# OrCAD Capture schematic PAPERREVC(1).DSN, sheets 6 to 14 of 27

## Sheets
6 PAGE1 (6): block FPGA32/ADC1, another copy of sheet 4
7 PAGE1 (7): size A; title: SNAP, BOARD LAYOUT and Change Log
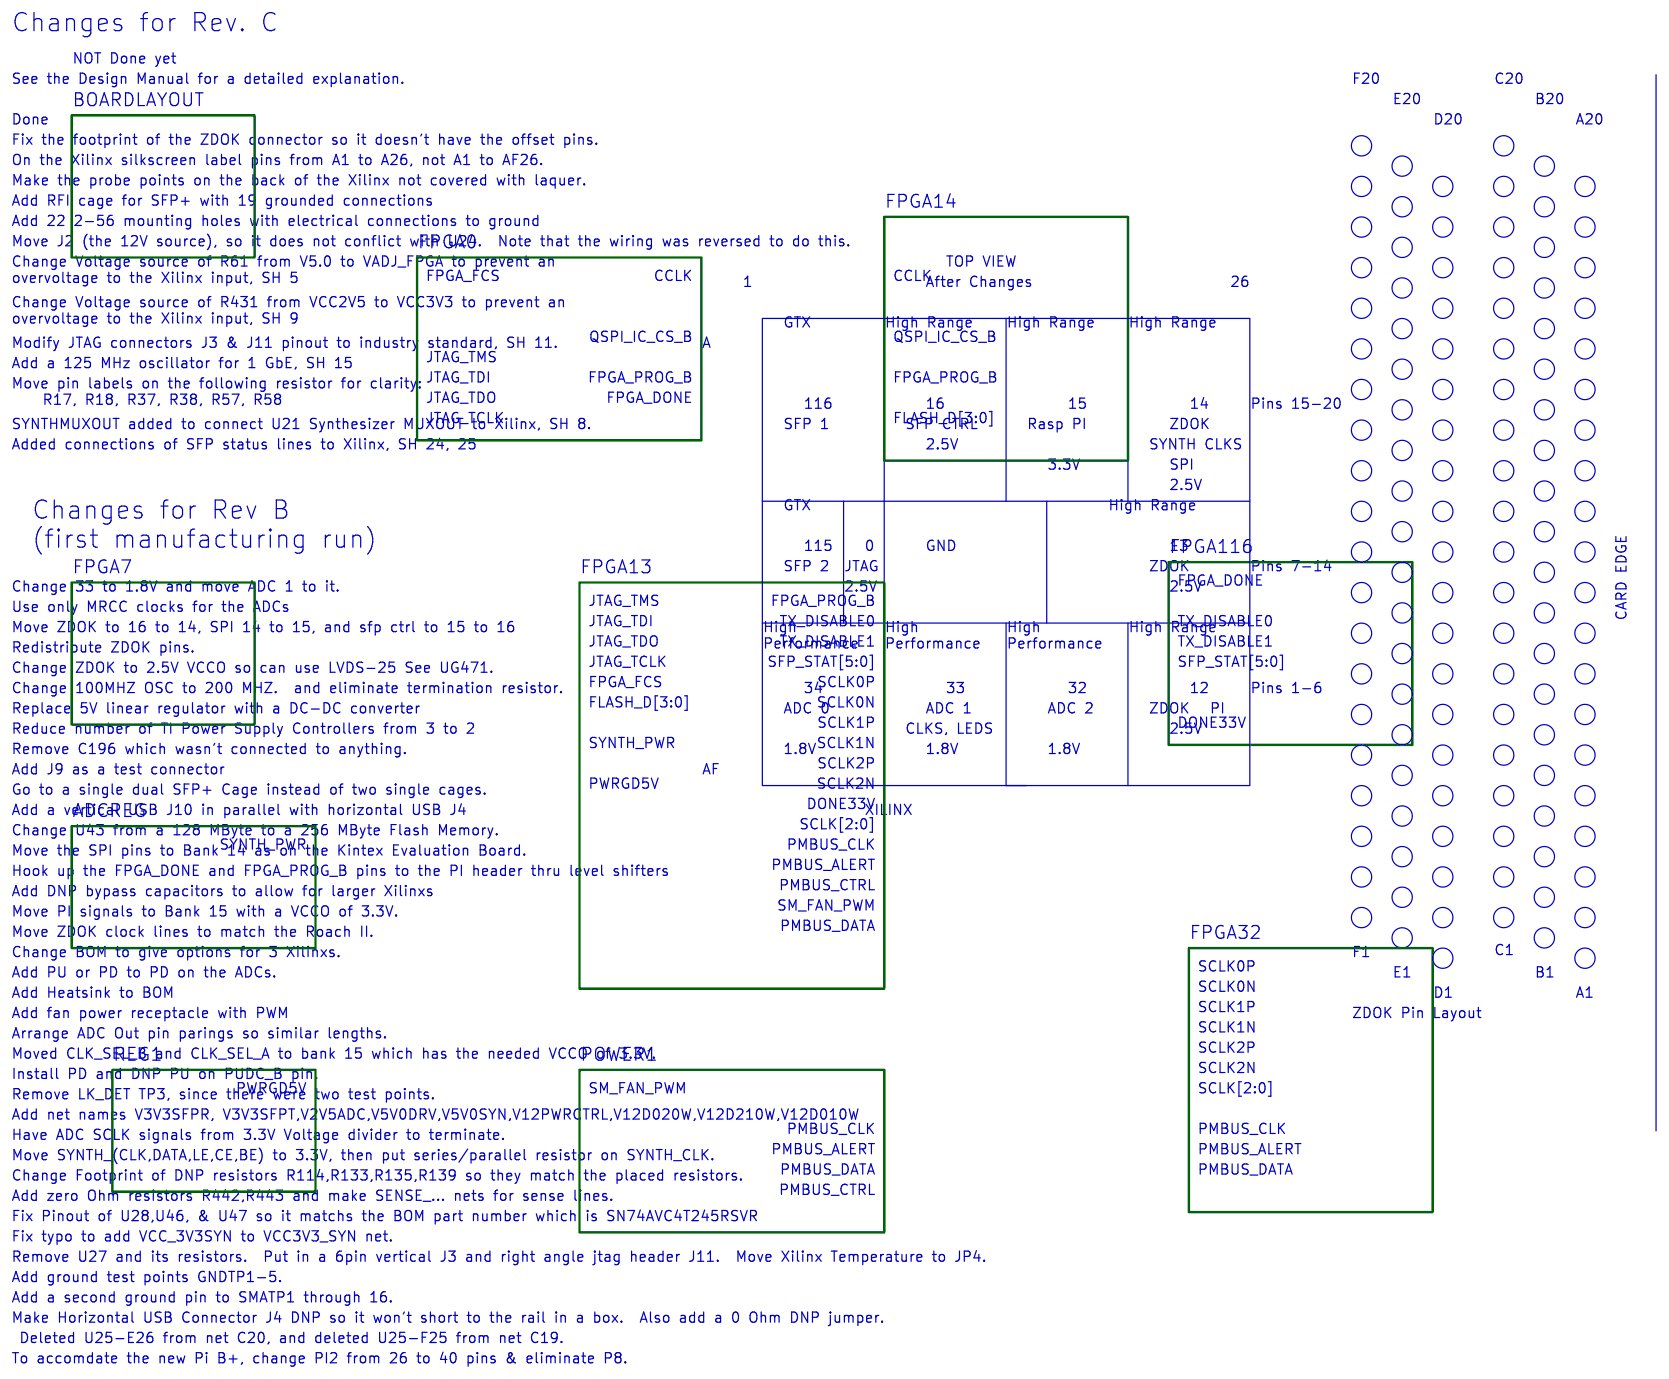
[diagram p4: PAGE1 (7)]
8 PAGE1 (8): size A; title: SNAP, FPGA Regulators; company: NRAO; block REG1
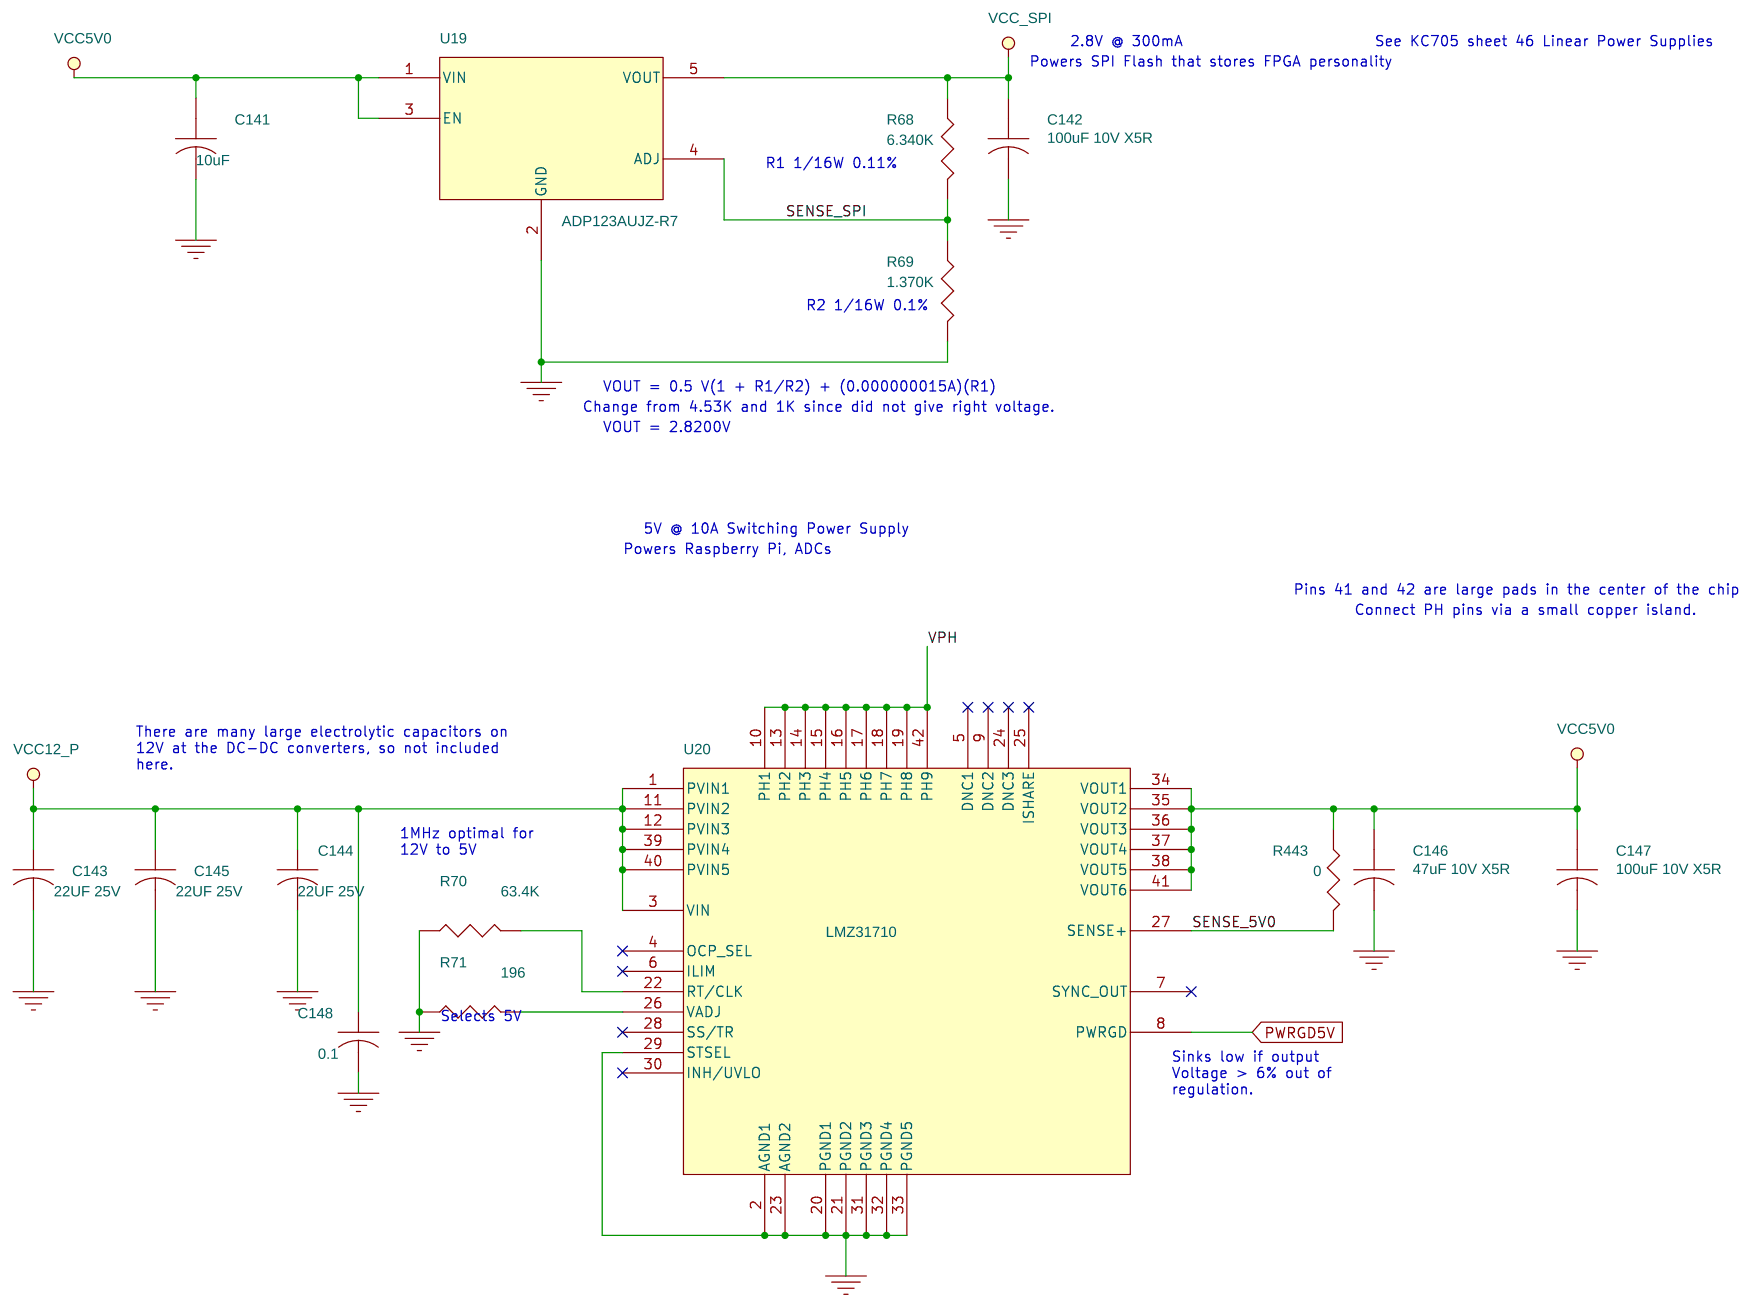
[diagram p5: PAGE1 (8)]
9 PAGE1 (9): size B; title: SNAP, FPGA POWER; block FPGA7
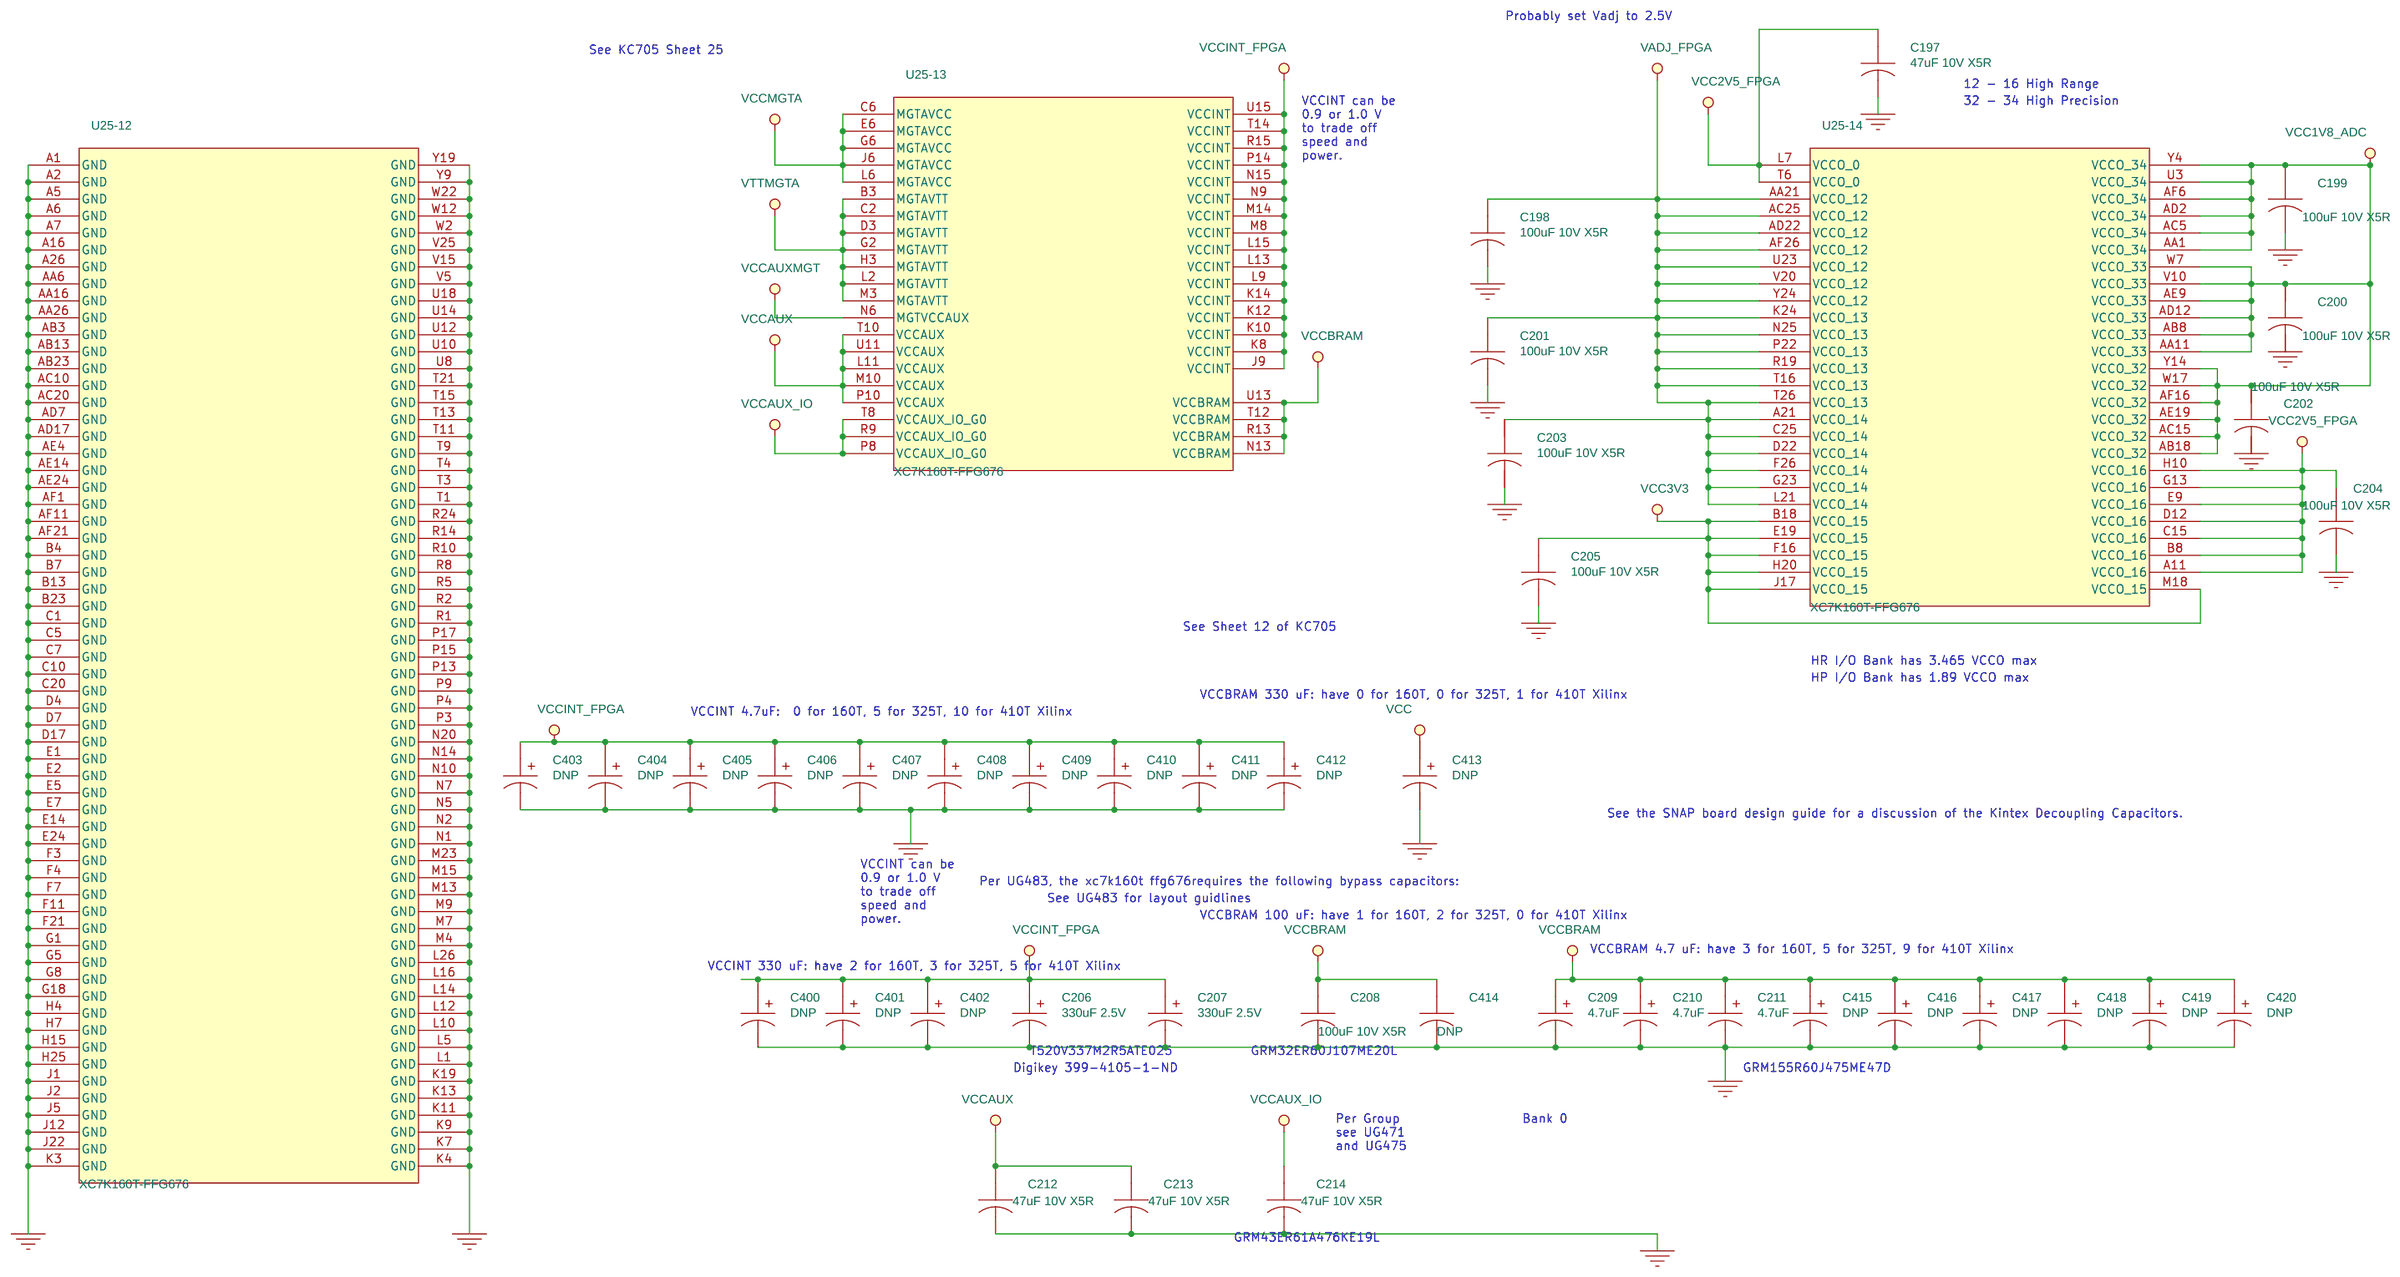
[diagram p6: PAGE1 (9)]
10 PAGE1 (10): size B; title: SNAP, SFP+ Connector and Cage; block FPGA116
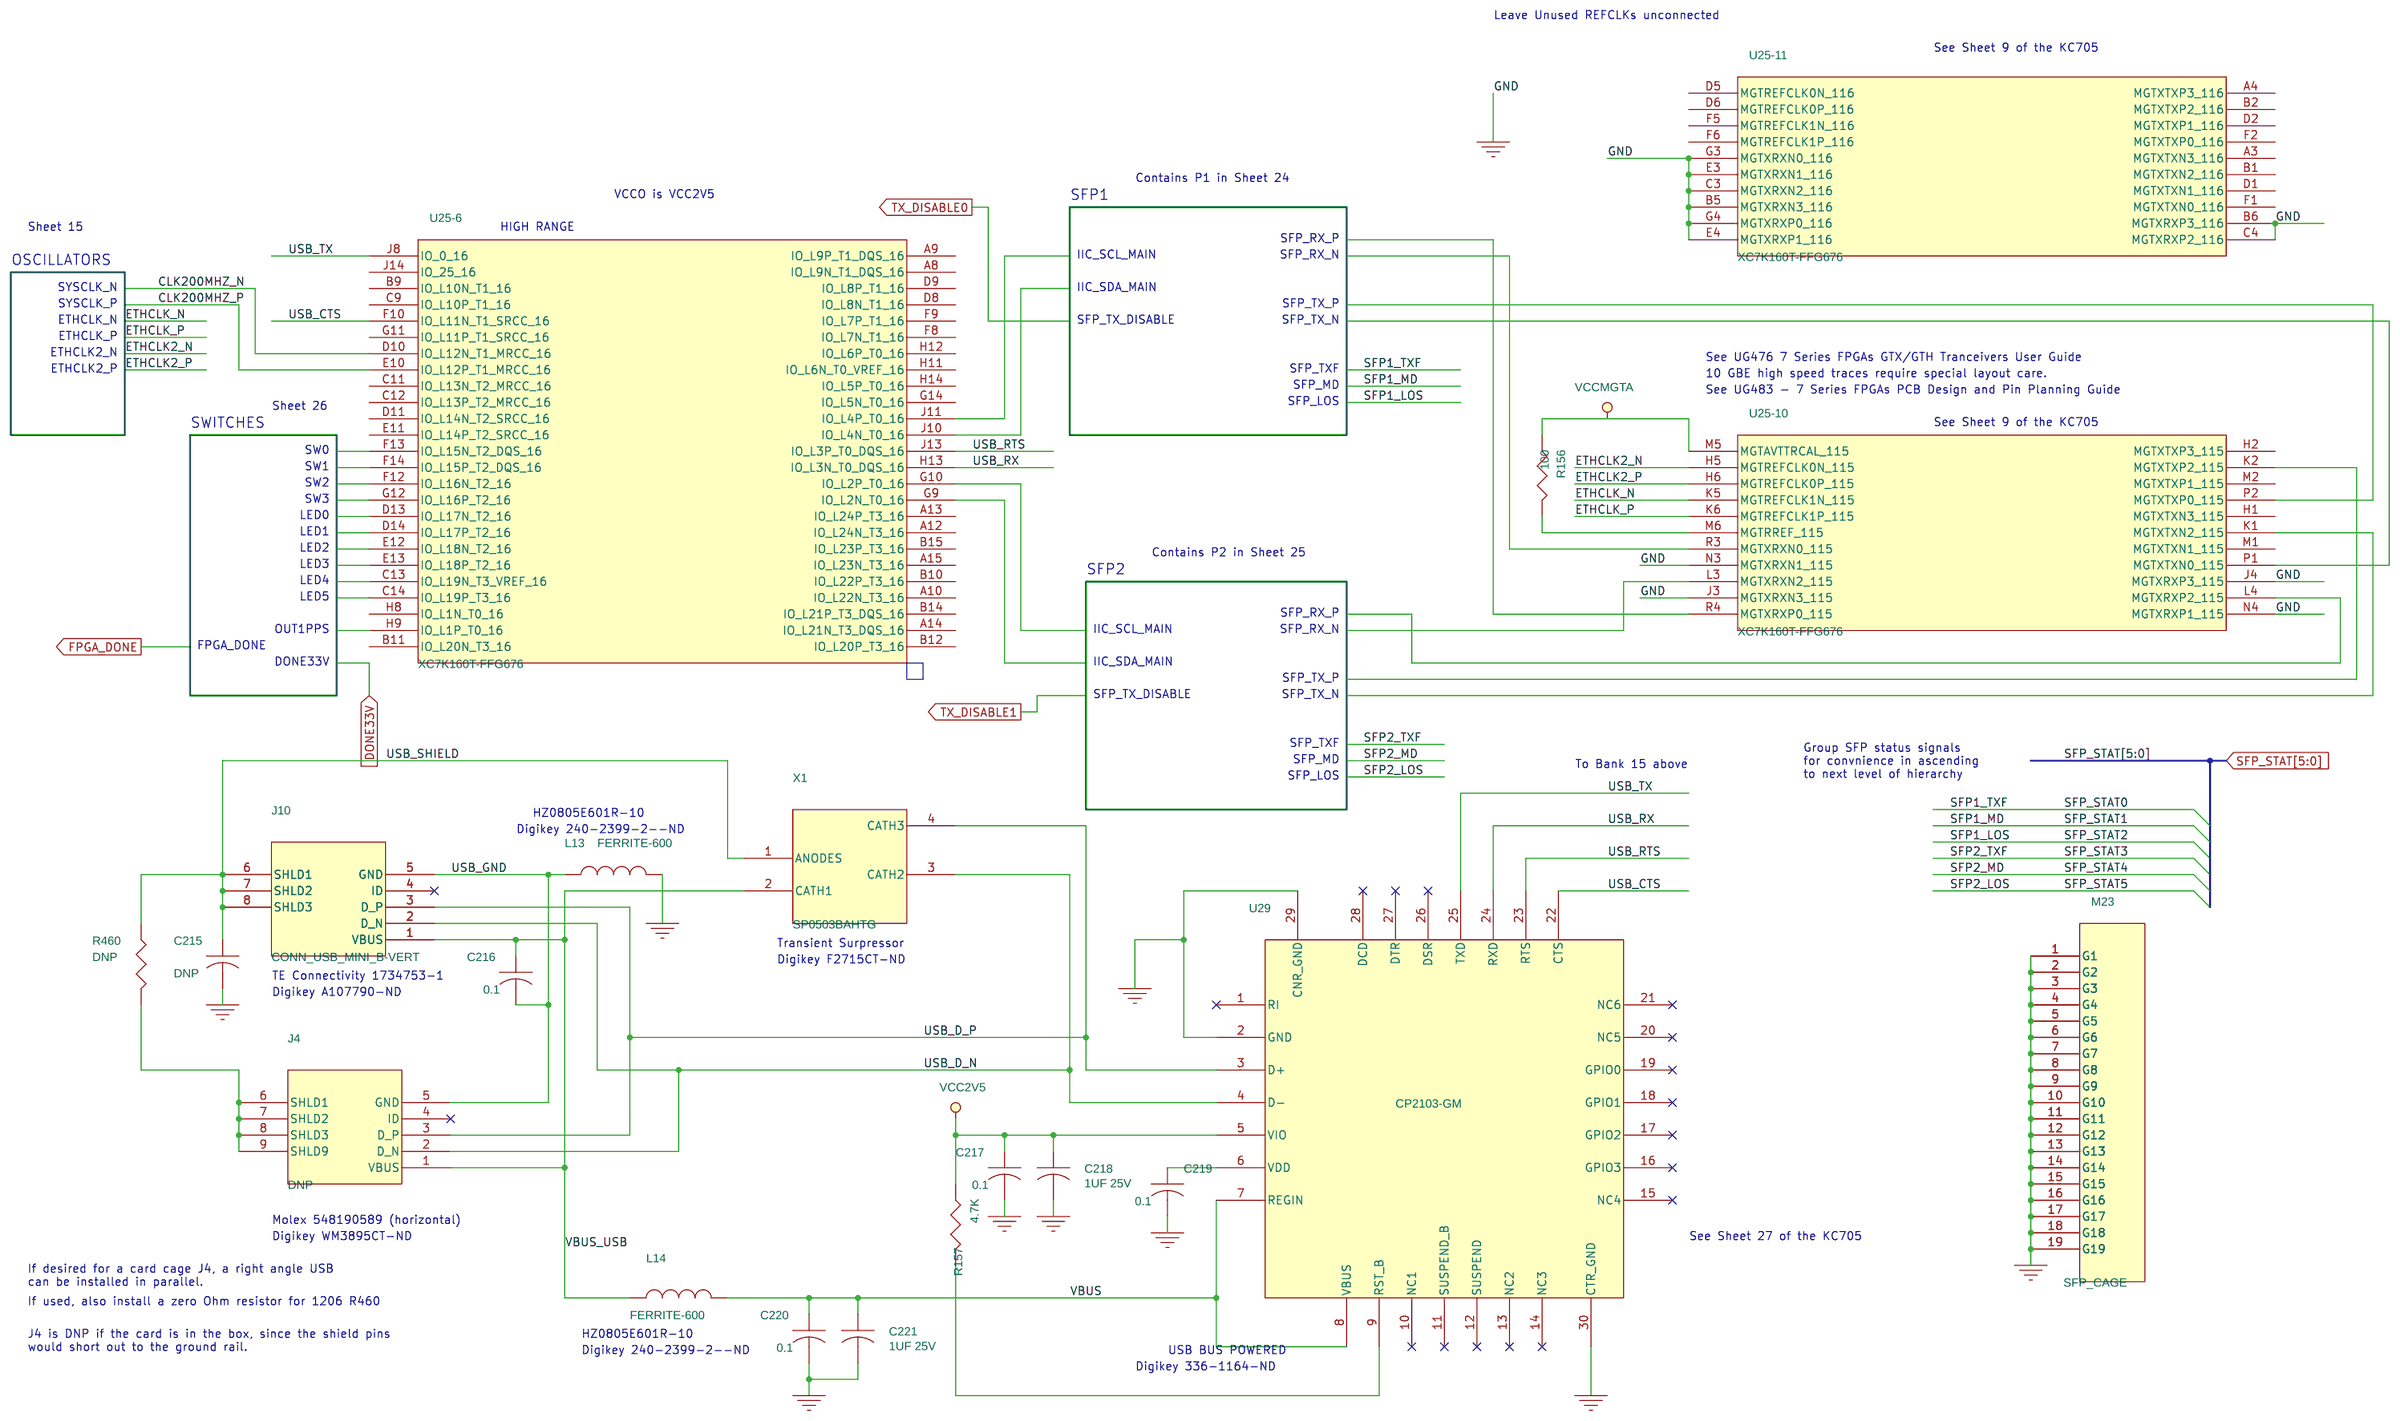
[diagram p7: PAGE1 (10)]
11 PAGE1 (11): size B; title: SNAP, SFP CONNECTOR; block FPGA116/SFP1
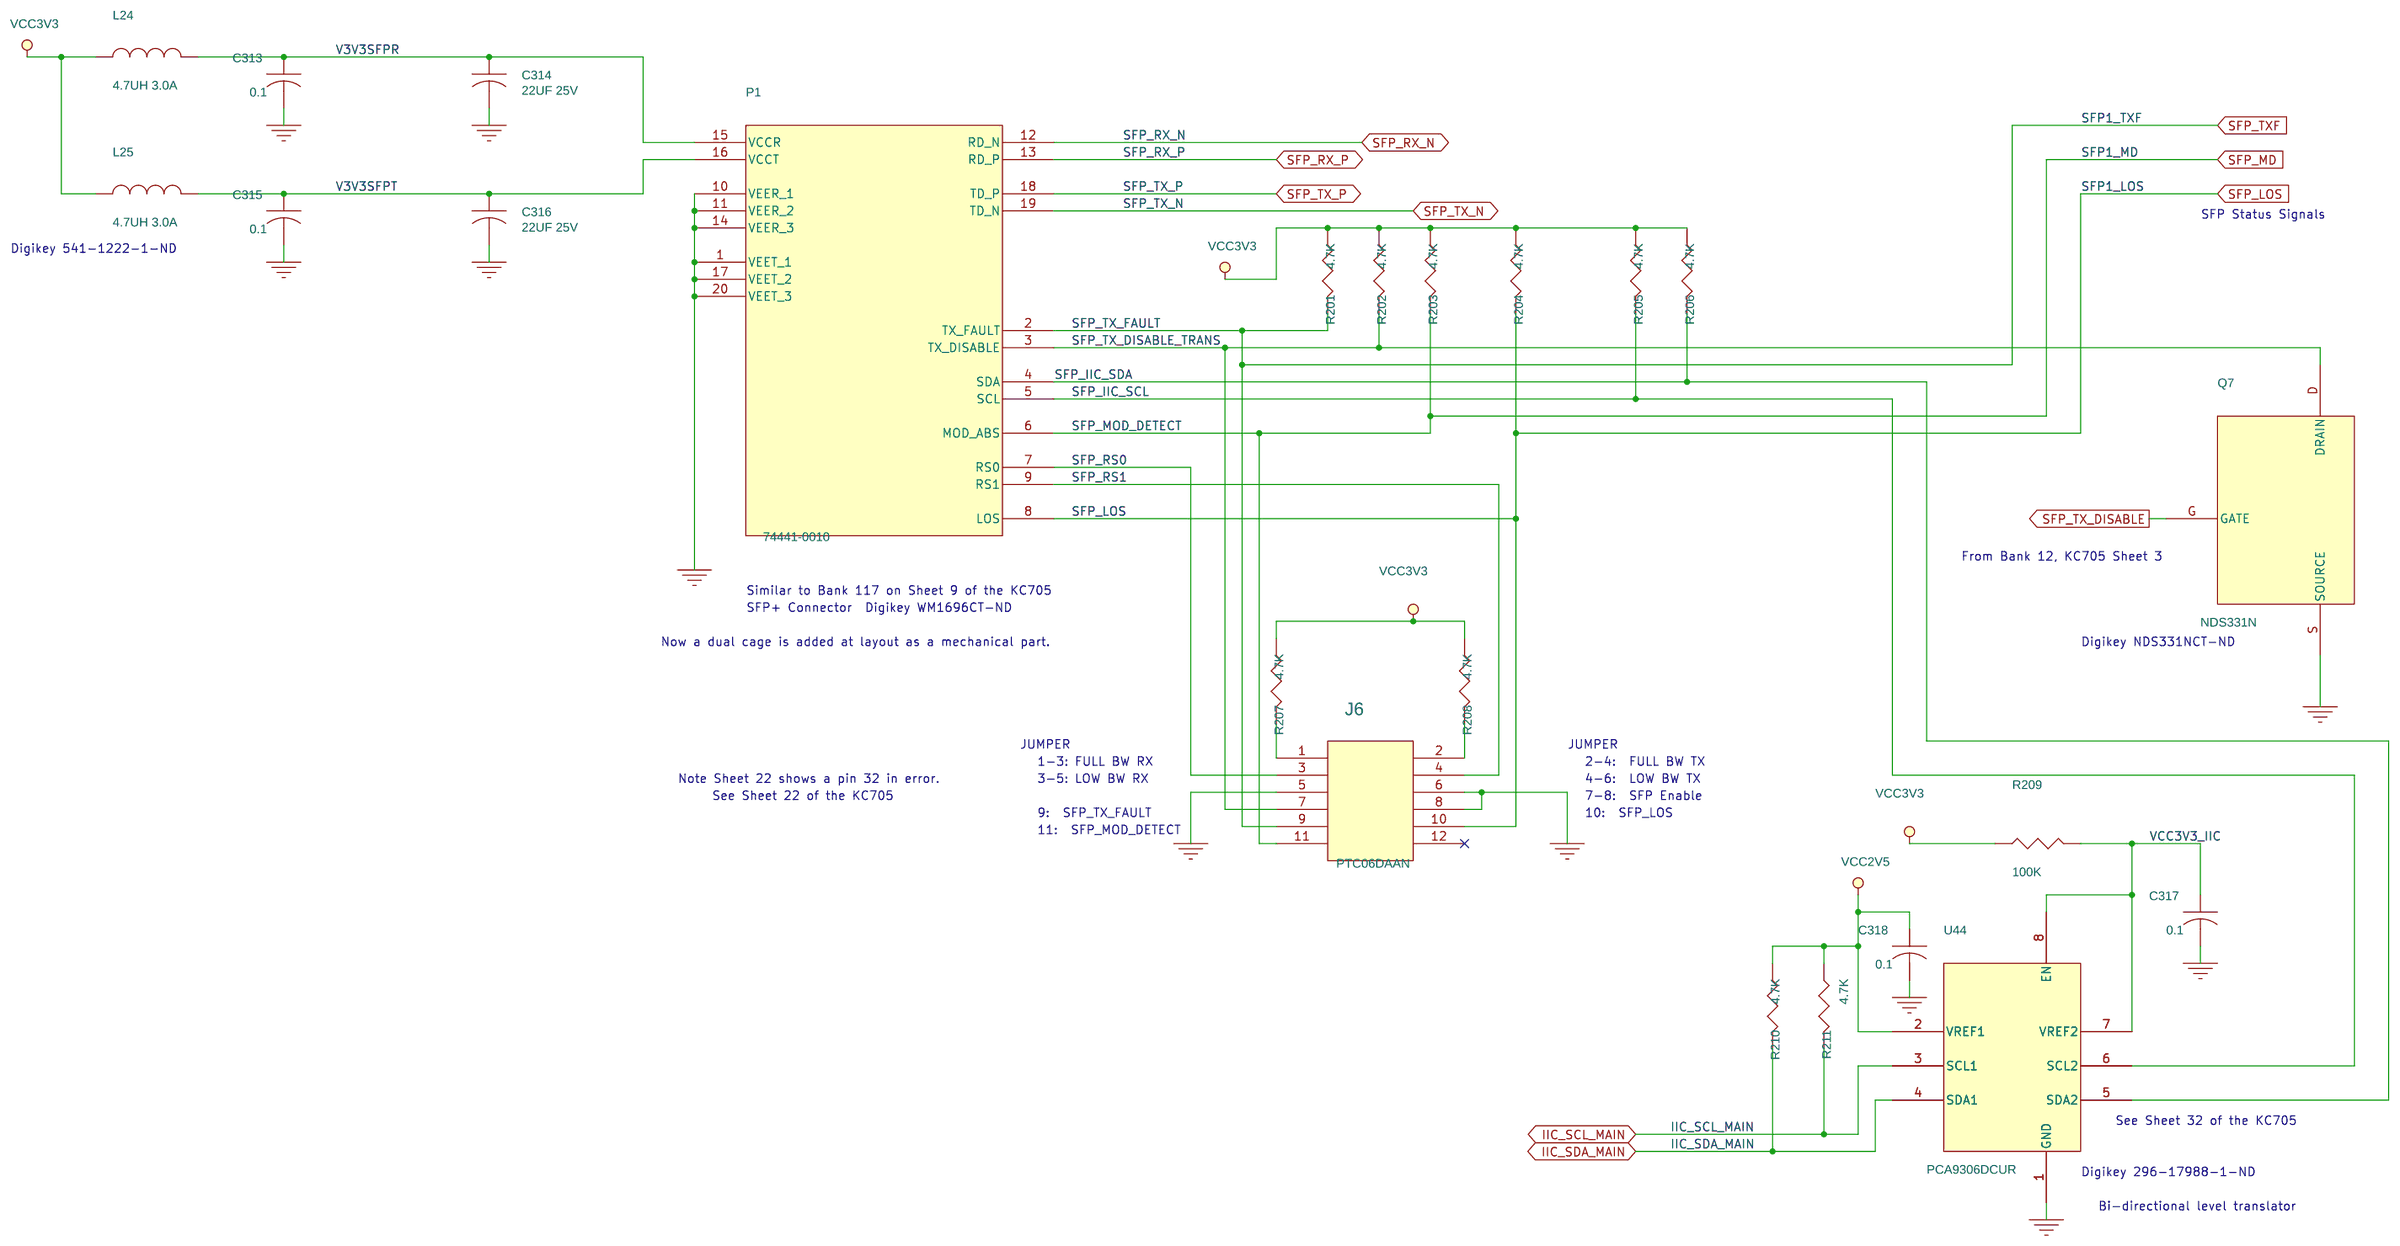
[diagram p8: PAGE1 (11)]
12 PAGE1 (12): size A; title: SNAP, Oscillators; block FPGA116/OSCILLATORS
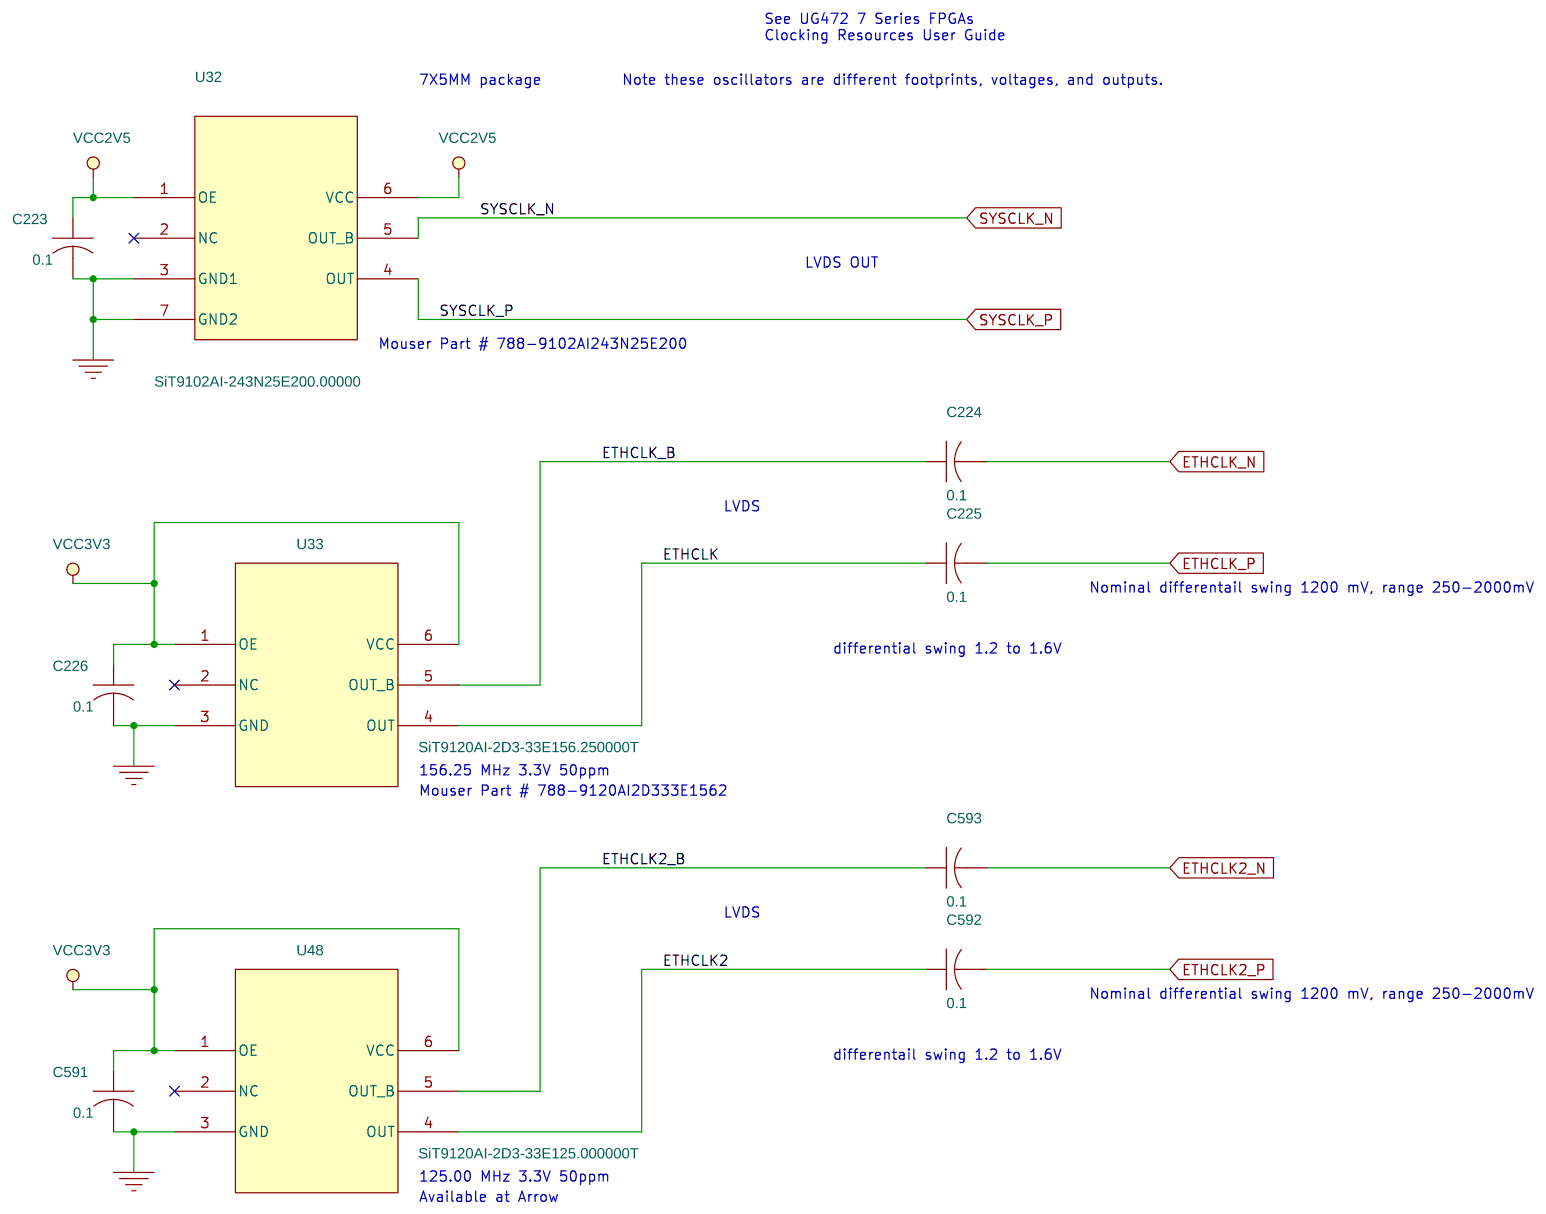
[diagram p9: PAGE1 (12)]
13 PAGE1 (13): block FPGA116/SFP2, another copy of sheet 11
14 PAGE1 (14): size B; title: SNAP, SWITCHES AND LEDS; block FPGA116/SWITCHES
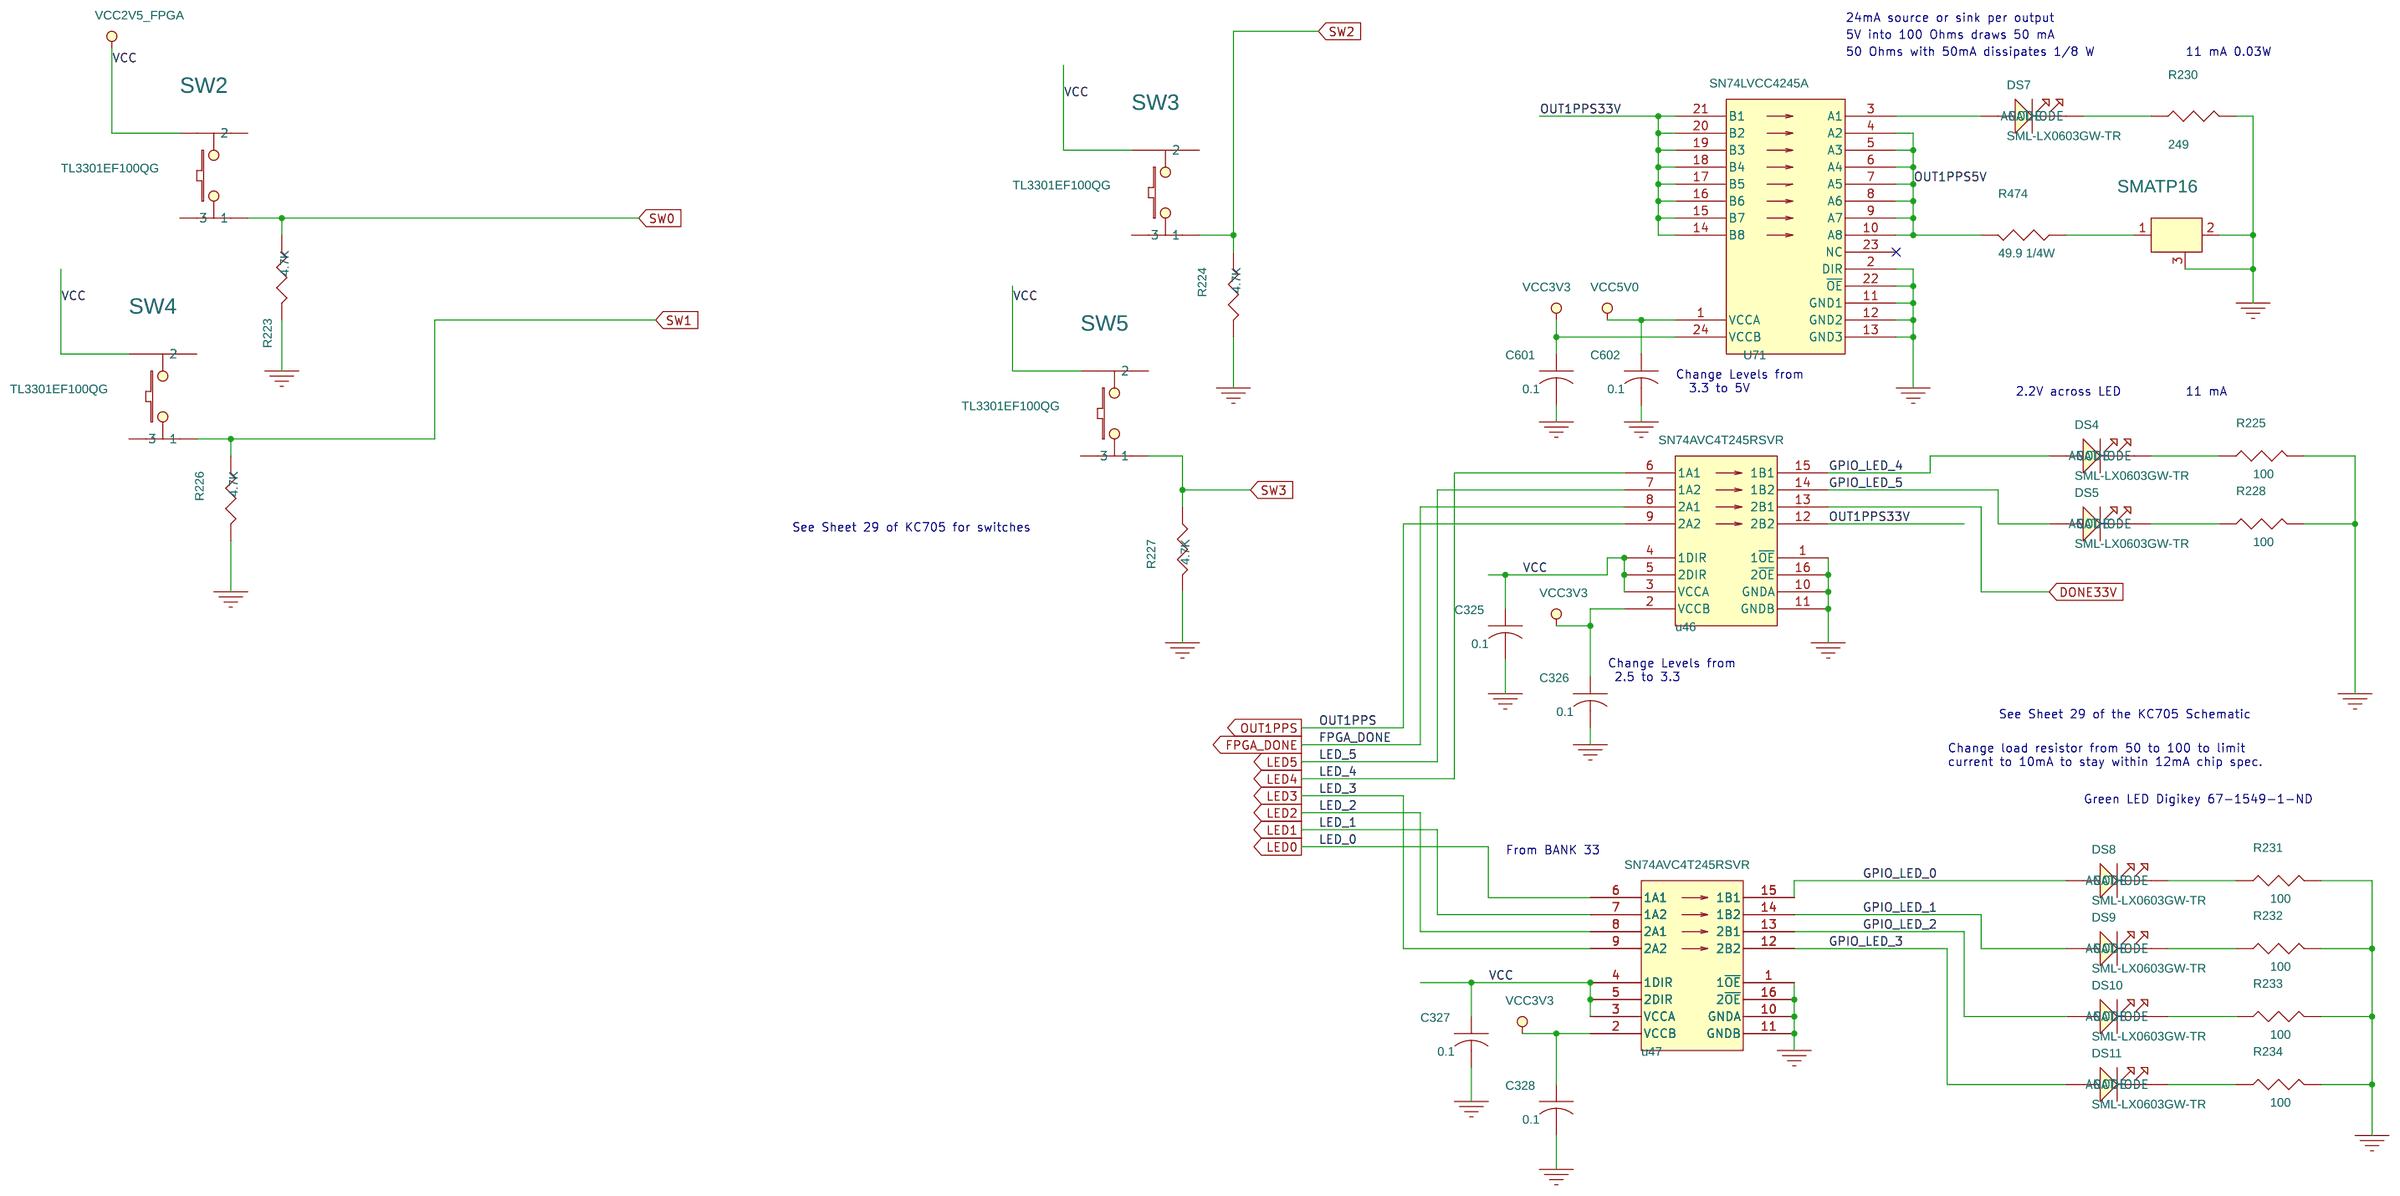
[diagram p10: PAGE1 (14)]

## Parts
sheet PAGE1 (3)
U25  XC7K160T-FFG676  [bga676c100p26x26_2700x2700x260]  (sections -1,-10,-11,-12,-13,-14,-2,-3,-4,-5,-6,-7,-8,-9)
sheet PAGE1 (6)
C40  1nf  [CAPC1005X50L]
C41  DNP  [CAPC1005X50L]
C42  1nf  [CAPC1005X50L]
C43  10nf  [CAPC1005X50L]
C44  100pf  [CAPC1005X50L]
C45  1nf  [CAPC1005X50L]
C46  10nf  [CAPC1005X50L]
C47  100pf  [CAPC1005X50L]
C48  DNP  [CAPC1005X50L]
C49  1nf  [CAPC1005X50L]
C50  1nf  [CAPC1005X50L]
C51  10nf  [CAPC1005X50L]
C52  100pf  [CAPC1005X50L]
C53  DNP  [CAPC1005X50L]
C54  1nf  [CAPC1005X50L]
C55  1nf  [CAPC1005X50L]
C56  DNP  [CAPC1005X50L]
C57  10nf  [CAPC1005X50L]
C58  100pf  [CAPC1005X50L]
C59  1nf  [CAPC1005X50L]
C60  1uF  [CAPC1608X90N]
C61  10nf  [CAPC1005X50L]
C62  1uF  [CAPC1608X90N]
C63  10nF  [CAPC1005X50L]
C64  1nf  [CAPC1005X50L]
C65  10nF  [CAPC1005X50L]
C66  1nf  [CAPC1005X50L]
C67  0.1uF  [CAPC1005X50L]
C68  1uF  [CAPC1608X90N]
C69  10nF  [CAPC1005X50L]
C70  1nf  [CAPC1005X50L]
C71  1uF  [CAPC1608X90N]
C72  10nf  [CAPC1005X50L]
C73  1uF  [CAPC1608X90N]
C74  10nf  [CAPC1005X50L]
C75  10nf  [CAPC1005X50L]
C76  220pf  [CAPC1005X50L]
C77  1uF  [CAPC1608X90N]
C78  10nf  [CAPC1005X50L]
L3  1uH  [INDM4532X340N]
L4  1uH  [INDM4532X340N]
R21  10.0  [RESC1005X35N]
R22  15.0  [RESC1005X35N]
R23  15.0  [RESC1005X35N]
R24  15.0  [RESC1005X35N]
R25  10.0  [RESC1005X35N]
R26  10.0  [RESC1005X35N]
R27  15.0  [RESC1005X35N]
R28  10.0  [RESC1005X35N]
R29  10.0  [RESC1005X35N]
R30  15.0  [RESC1005X35N]
R31  15.0  [RESC1005X35N]
R32  10.0  [RESC1005X35N]
R33  10.0  [RESC1005X35N]
R34  15.0  [RESC1005X35N]
R35  15.0  [RESC1005X35N]
R36  10.0  [RESC1005X35N]
R37  1K  [RESC1005X35N]
R38  1K  [RESC1005X35N]
R39  49.9  [RESC1005X35N]
R40  49.9  [RESC1005X35N]
R423  4.7K  [RESC1005X35N]
R424  4.7K  [RESC1005X35N]
R425  DNP  [RESC1005X35N]
R440  120  [RESC1608X50N]
T5  TC1-1-13MG2+  [XFMR_TC1-1-13MG2]
T6  TC1-1-13MG2+  [XFMR_TC1-1-13MG2]
T7  TC1-1-13MG2+  [XFMR_TC1-1-13MG2]
T8  TC1-1-13MG2+  [XFMR_TC1-1-13MG2]
U6  ATTEN  [RESCAF65P100X100X45-4N]
U7  HMCAD1511  [QFN50P700X700X100-49T540X540L]
U8  ATTEN  [RESCAF65P100X100X45-4N]
U9  ATTEN  [RESCAF65P100X100X45-4N]
U10  ATTEN  [RESCAF65P100X100X45-4N]
sheet PAGE1 (8)
C141  10uF  [CAPC3216X180N]
C142  100uF 10V X5R  [CAPC3225X270N]
C143  22UF 25V  [CAPC3216X180N]
C144  22UF 25V  [CAPC3216X180N]
C145  22UF 25V  [CAPC3216X180N]
C146  47uF 10V X5R  [CAPC3216X180N]
C147  100uF 10V X5R  [CAPC3225X270N]
C148  0.1  [CAPC1005X50L]
R68  6.340K  [RESC1608X50N]
R69  1.370K  [RESC1608X50N]
R70  63.4K  [RESC1005X35N]
R71  196  [RESC1005X35N]
R443  0  [RESC1005X35N]
U19  ADP123AUJZ-R7  [SOT95P280X145-5N]
U20  LMZ31710  [QFN80P1000X1000X440-42T320X130x2N-ALT1]
sheet PAGE1 (9)
C197  47uF 10V X5R  [CAPC3216X180N]
C198  100uF 10V X5R  [CAPC3225X270N]
C199  100uF 10V X5R  [CAPC3225X270N]
C200  100uF 10V X5R  [CAPC3225X270N]
C201  100uF 10V X5R  [CAPC3225X270N]
C202  100uF 10V X5R  [CAPC3225X270N]
C203  100uF 10V X5R  [CAPC3225X270N]
C204  100uF 10V X5R  [CAPC3225X270N]
C205  100uF 10V X5R  [CAPC3225X270N]
C206  330uF 2.5V  [CAPMP7343X180N-ALT1]
C207  330uF 2.5V  [CAPMP7343X180N-ALT1]
C208  100uF 10V X5R  [CAPC3225X270N]
C209  4.7uF  [CAPC2012X140N]
C210  4.7uF  [CAPC2012X140N]
C211  4.7uF  [CAPC2012X140N]
C212  47uF 10V X5R  [CAPC3216X180N]
C213  47uF 10V X5R  [CAPC3216X180N]
C214  47uF 10V X5R  [CAPC3216X180N]
C400  DNP  [CAPMP7343X180N-ALT1]
C401  DNP  [CAPMP7343X180N-ALT1]
C402  DNP  [CAPMP7343X180N-ALT1]
C403  DNP  [CAPC2012X140N]
C404  DNP  [CAPC2012X140N]
C405  DNP  [CAPC2012X140N]
C406  DNP  [CAPC2012X140N]
C407  DNP  [CAPC2012X140N]
C408  DNP  [CAPC2012X140N]
C409  DNP  [CAPC2012X140N]
C410  DNP  [CAPC2012X140N]
C411  DNP  [CAPC2012X140N]
C412  DNP  [CAPC2012X140N]
C413  DNP  [CAPMP7343X180N-ALT1]
C414  DNP  [CAPC3225X270N]
C415  DNP  [CAPC2012X140N]
C416  DNP  [CAPC2012X140N]
C417  DNP  [CAPC2012X140N]
C418  DNP  [CAPC2012X140N]
C419  DNP  [CAPC2012X140N]
C420  DNP  [CAPC2012X140N]
sheet PAGE1 (10)
C215  DNP  [CAPC1608X90N]
C216  0.1  [CAPC1005X50L]
C217  0.1  [CAPC1005X50L]
C218  1UF 25V  [CAPC1608X90N]
C219  0.1  [CAPC1005X50L]
C220  0.1  [CAPC1005X50L]
C221  1UF 25V  [CAPC1608X90N]
J4  DNP  [MOLEX_548190589]
J10  CONN_USB_MINI_B-VERT  [TECONN_1734753-1]
L13  FERRITE-600  [INDC2012X110N]
L14  FERRITE-600  [INDC2012X110N]
M23  SFP_CAGE  [MOLEX_SD-74754-0220]
R156  100  [RESC1005X35N]
R157  4.7K  [RESC1005X35N]
R460  DNP  [RESC3216X70N]
U29  CP2103-GM  [QFN50P500X500X100-28N]
X1  SP0503BAHTG  [SOT143R]
sheet PAGE1 (11)
C313  0.1  [CAPC1005X50L]
C314  22UF 25V  [CAPC3216X180N]
C315  0.1  [CAPC1005X50L]
C316  22UF 25V  [CAPC3216X180N]
C317  0.1  [CAPC1005X50L]
C318  0.1  [CAPC1005X50L]
J6  PTC06DAAN  [HDRV6X2]
L24  4.7UH 3.0A  [INDM5551X200N]
L25  4.7UH 3.0A  [INDM5551X200N]
P1  74441-0010  [MOLEX_744410010]
Q7  NDS331N  [SOT95P237X100-4]
R201  4.7K  [RESC1005X35N]
R202  4.7K  [RESC1005X35N]
R203  4.7K  [RESC1005X35N]
R204  4.7K  [RESC1005X35N]
R205  4.7K  [RESC1005X35N]
R206  4.7K  [RESC1005X35N]
R207  4.7K  [RESC1005X35N]
R208  4.7K  [RESC1005X35N]
R209  100K  [RESC1005X35N]
R210  4.7K  [RESC1005X35N]
R211  4.7K  [RESC1005X35N]
U44  PCA9306DCUR  [SOP50P310X90-8N]
sheet PAGE1 (12)
C223  0.1  [CAPC1005X50L]
C224  0.1  [CAPC1005X50L]
C225  0.1  [CAPC1005X50L]
C226  0.1  [CAPC1005X50L]
C591  0.1  [CAPC1005X50L]
C592  0.1  [CAPC1005X50L]
C593  0.1  [CAPC1005X50L]
U32  SiT9102AI-243N25E200.00000  [OSC254P700X500X90-7T147X230N]
U33  SiT9120AI-2D3-33E156.250000T  [OSC254P700X500X90-6N]
U48  SiT9120AI-2D3-33E125.000000T  [OSC254P700X500X90-6N]
sheet PAGE1 (13)
C319  0.1  [CAPC1005X50L]
C320  22UF 25V  [CAPC3216X180N]
C321  0.1  [CAPC1005X50L]
C322  22UF 25V  [CAPC3216X180N]
C323  0.1  [CAPC1005X50L]
C324  0.1  [CAPC1005X50L]
J7  PTC06DAAN  [HDRV6X2]
L26  4.7UH 3.0A  [INDM5551X200N]
L27  4.7UH 3.0A  [INDM5551X200N]
P2  74441-0010  [MOLEX_744410010]
Q8  NDS331N  [SOT95P237X100-4]
R212  4.7K  [RESC1005X35N]
R213  4.7K  [RESC1005X35N]
R214  4.7K  [RESC1005X35N]
R215  4.7K  [RESC1005X35N]
R216  4.7K  [RESC1005X35N]
R217  4.7K  [RESC1005X35N]
R218  4.7K  [RESC1005X35N]
R219  4.7K  [RESC1005X35N]
R220  100K  [RESC1005X35N]
R221  4.7K  [RESC1005X35N]
R222  4.7K  [RESC1005X35N]
U45  PCA9306DCUR  [SOP50P310X90-8N]
sheet PAGE1 (14)
C325  0.1  [CAPC1005X50L]
C326  0.1  [CAPC1005X50L]
C327  0.1  [CAPC1005X50L]
C328  0.1  [CAPC1005X50L]
C601  0.1  [CAPC1005X50L]
C602  0.1  [CAPC1005X50L]
DS4  SML-LX0603GW-TR  [LEDM180X60X60N]
DS5  SML-LX0603GW-TR  [LEDM180X60X60N]
DS7  SML-LX0603GW-TR  [LEDM180X60X60N]
DS8  SML-LX0603GW-TR  [LEDM180X60X60N]
DS9  SML-LX0603GW-TR  [LEDM180X60X60N]
DS10  SML-LX0603GW-TR  [LEDM180X60X60N]
DS11  SML-LX0603GW-TR  [LEDM180X60X60N]
R223  4.7K  [RESC1005X35N]
R224  4.7K  [RESC1005X35N]
R225  100  [RESC1005X35N]
R226  4.7K  [RESC1005X35N]
R227  4.7K  [RESC1005X35N]
R228  100  [RESC1005X35N]
R230  249  [RESC1005X35N]
R231  100  [RESC1005X35N]
R232  100  [RESC1005X35N]
R233  100  [RESC1005X35N]
R234  100  [RESC1005X35N]
R474  49.9 1/4W  [RESC3216X70N]
SMATP16  SMATP  [SMA_END_LAUNCH]
SW2  TL3301EF100QG  [SW_TL3301EF100QG]
SW3  TL3301EF100QG  [SW_TL3301EF100QG]
SW4  TL3301EF100QG  [SW_TL3301EF100QG]
SW5  TL3301EF100QG  [SW_TL3301EF100QG]
u46  SN74AVC4T245RSVR  [QFN40P260X180X55-16L]
u47  SN74AVC4T245RSVR  [QFN40P260X180X55-16L]
U71  SN74LVCC4245A  [SOP65P640X120-24L25N]

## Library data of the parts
U25 = XC7K160T-FFG676
C40 = CAP_NP_27: Digikey PN: 399-10034-6-ND; ESR: NA; Size: 0402; Temp. Coef.: NPO (COG); Tolerance: 5%; Voltage Rating: 50 V
C41 C48 C53 C56 = CAP_NP_2: ESR: NA; Size: 0402; Temp. Coef.: NPO (COG); Tolerance: 5%; Voltage Rating: 50 V
C42 = CAP_NP_28: Digikey PN: 399-10034-6-ND; ESR: NA; Size: 0402; Temp. Coef.: NPO (COG); Tolerance: 5%; Voltage Rating: 50 V
C43 C46 C51 C57 = CAP_NP_35: Digikey PN: 399-3066-6-ND; ESR: NA; Size: 0402; Temp. Coef.: X7R; Tolerance: 10%; Voltage Rating: 25 V
C44 C47 C52 C58 = CAP_NP_36: Digikey PN: 399-1022-6-ND; ESR: NA; Size: 0402; Temp. Coef.: NPO (COG); Tolerance: 5%; Voltage Rating: 50 V
C45 = CAP_NP_29: Digikey PN: 399-10034-6-ND; ESR: NA; Size: 0402; Temp. Coef.: NPO (COG); Tolerance: 5%; Voltage Rating: 50 V
C49 = CAP_NP_30: Digikey PN: 399-10034-6-ND; ESR: NA; Size: 0402; Temp. Coef.: NPO (COG); Tolerance: 5%; Voltage Rating: 50 V
C50 = CAP_NP_31: Digikey PN: 399-10034-6-ND; ESR: NA; Size: 0402; Temp. Coef.: NPO (COG); Tolerance: 5%; Voltage Rating: 50 V
C54 = CAP_NP_32: Digikey PN: 399-10034-6-ND; ESR: NA; Size: 0402; Temp. Coef.: NPO (COG); Tolerance: 5%; Voltage Rating: 50 V
C55 = CAP_NP_33: Digikey PN: 399-10034-6-ND; ESR: NA; Size: 0402; Temp. Coef.: NPO (COG); Tolerance: 5%; Voltage Rating: 50 V
C59 = CAP_NP_34: Digikey PN: 399-10034-6-ND; ESR: NA; Size: 0402; Temp. Coef.: NPO (COG); Tolerance: 5%; Voltage Rating: 50 V
C60 = CAP_NP_5: Digikey PN: 399-3118-6-ND; Size: 0603; Temp. Coef.: X5R; Tolerance: 10%; Voltage Rating: 10V
C61 = CAP_NP_6: Digikey PN: 399-3066-6-ND; ESR: NA; Size: 0402; Temp. Coef.: X7R; Tolerance: 10%; Voltage Rating: 25 V
C62 = CAP_NP_9: Digikey PN: 399-3118-6-ND; Size: 0603; Temp. Coef.: X5R; Tolerance: 10%; Voltage Rating: 10V
C63 = CAP_NP_10: Digikey PN: 399-3066-6-ND; ESR: NA; Size: 0402; Temp. Coef.: X7R; Tolerance: 10%; Voltage Rating: 25 V
C64 = CAP_NP_11: Digikey PN: 399-1032-1-ND; Size: 0402; Temp. Coef.: X7R; Tolerance: 10%; Voltage Rating: 25 V
C65 = CAP_NP_12: Digikey PN: 399-3066-6-ND; ESR: NA; Size: 0402; Temp. Coef.: X7R; Tolerance: 10%; Voltage Rating: 25 V
C66 = CAP_NP_13: Digikey PN: 399-1032-1-ND; Size: 0402; Temp. Coef.: X7R; Tolerance: 10%; Voltage Rating: 25 V
C67 = CAP_NP_23: ESR: NA; Size: 0402; Temp. Coef.: X5R; Tolerance: 10%; Voltage Rating: 10 V
C68 = CAP_NP_14: Digikey PN: 399-3118-6-ND; Size: 0603; Temp. Coef.: X5R; Tolerance: 10%; Voltage Rating: 10V
C69 = CAP_NP_15: Digikey PN: 399-3066-6-ND; ESR: NA; Size: 0402; Temp. Coef.: X7R; Tolerance: 10%; Voltage Rating: 25 V
C70 = CAP_NP_0: Digikey PN: 399-1032-1-ND; Size: 0402; Temp. Coef.: X7R; Tolerance: 10%; Voltage Rating: 25 V
C71 = CAP_NP_7: Digikey PN: 399-3118-6-ND; Size: 0603; Temp. Coef.: X5R; Tolerance: 10%; Voltage Rating: 10V
C72 = CAP_NP_8: Digikey PN: 399-3066-6-ND; ESR: NA; Size: 0402; Temp. Coef.: X7R; Tolerance: 10%; Voltage Rating: 25 V
C73 = CAP_NP_17: Digikey PN: 399-3118-6-ND; Size: 0603; Temp. Coef.: X5R; Tolerance: 10%; Voltage Rating: 10V
C74 = CAP_NP_18: Digikey PN: 399-3066-6-ND; ESR: NA; Size: 0402; Temp. Coef.: X7R; Tolerance: 10%; Voltage Rating: 25 V
C75 = CAP_NP_19: Digikey PN: 399-3066-6-ND; ESR: NA; Size: 0402; Temp. Coef.: X7R; Tolerance: 10%; Voltage Rating: 25 V
C76 = CAP_NP_22: Digikey PN: 399-7776-6-ND; ESR: NA; Size: 0402; Temp. Coef.: NPO; Tolerance: 5%; Voltage Rating: 50 V
C77 = CAP_NP_20: Digikey PN: 399-3118-6-ND; Size: 0603; Temp. Coef.: X5R; Tolerance: 10%; Voltage Rating: 10V
C78 = CAP_NP_21: Digikey PN: 399-3066-6-ND; ESR: NA; Size: 0402; Temp. Coef.: X7R; Tolerance: 10%; Voltage Rating: 25 V
L3 L4 = INDUCTOR: Current Rating: 1.05 A; DC Resistance: 0.11 ohms; Digikey PN: NLC453232T-1R0K-PF; Part No.: NLC453232T-150K-PF; Size: 1812; Tolerance: 10%; Vendor: TDK
R21 R25 R26 R28 R29 R32 R33 R36 = RESISTOR_SM_10: Digikey PN: 311-33.0LRDKR-ND; Power Rating: 1/16 W; Size: 0402; Temp. Coef.: +/- 100 PPM; Tolerance: 1%
R22 R24 R30 R34 = RESISTOR_SM_10: Digikey PN: 311-36.0LRDKR-ND; Power Rating: 1/16 W; Size: 0402; Temp. Coef.: +/- 100 PPM; Tolerance: 1%
R23 R27 R31 R35 = RESISTOR_SM_12: Digikey PN: 311-36.0LRDKR-ND; Power Rating: 1/16 W; Size: 0402; Temp. Coef.: +/- 100 PPM; Tolerance: 1%
R37 = RESISTOR_SM_4: Digikey PN: 311-1.00KLRCT-ND; Power Rating: 1/10 W; Size: 0402; Temp. Coef.: +/- 100 PPM; Tolerance: 1%
R38 = RESISTOR_SM_1: Digikey PN: 311-1.00KLRCT-ND; Power Rating: 1/10 W; Size: 0402; Temp. Coef.: +/- 100 PPM; Tolerance: 1%
R39 = RESISTOR_SM_20: Digikey PN: 311-49.9LRDKR-ND; Power Rating: 1/10 W; Size: 0402; Temp. Coef.: +/- 100 PPM; Tolerance: 1%
R40 = RESISTOR_SM_21: Digikey PN: 311-49.9LRDKR-ND; Power Rating: 1/10 W; Size: 0402; Temp. Coef.: +/- 100 PPM; Tolerance: 1%
R230 R423-R425 = RESISTOR_0: COMPHEIGHT: 0.000; DECOUPLER: NO; MEMORY: NO; POWER: 1/10W; PRECISION: 1%
R440 = RESISTOR_SM_1: Power Rating: 1/10 W; Size: 0603; Temp. Coef.: +/- 100 PPM; Tolerance: 1%
T5-T8 = TC1-1-13MG2+
U6 U8-U10 = ATTEN
U7 = HMCAD1511
C141 = CAPACITOR_POL_17
C142 C147 C198-C205 C208 C414 = CAPACITOR_POL_2
C143-C145 C148 C215-C221 C223-C226 C313-C328 C591-C593 C601 C602 = CAP_0
C146 C197 = CAPACITOR_POL_14
R68 = RESISTOR_0: COMPHEIGHT: 0.000; DECOUPLER: NO; MEMORY: NO; POWER: 1/16W; PRECISION: .11%
R69-R71 = RESISTOR_0: COMPHEIGHT: 0.000; DECOUPLER: NO; MEMORY: NO; POWER: 1/16W; PRECISION: .1%
R443 = RESISTOR_0: COMPHEIGHT: 0.000; DECOUPLER: NO; MEMORY: NO; POWER: 1/16W; PRECISION: 1%
U19 = 1_2_BRICK_21: COMPFIXED: NO; COMPGROUP: 0; COMPHEIGHT: 0.000; COMPKEY: NO; COMPLOC: [9600.000,-13400.000]; COMPLOCKED: NO; COMPROT: 0; COMPSIDE: TOP; DECOUPLER: NO; MEMORY: NO
U20 = 1_2_BRICK_35: COMPFIXED: NO; COMPGROUP: 0; COMPHEIGHT: 0.000; COMPKEY: NO; COMPLOC: [9600.000,-13400.000]; COMPLOCKED: NO; COMPROT: 0; COMPSIDE: TOP; DECOUPLER: NO; MEMORY: NO
C206 C400-C402 C413 = CAPACITOR_POL_0: Digikey: 399-4105-1-ND
C207 C209-C211 C403-C412 C415-C420 = CAPACITOR_POL_0
C212-C214 = CAPACITOR_POL_16
J4 = XC17256L_27
J10 = XC17256L_26
L13 L14 L24-L27 = INDUCTOR_0
M23 = SFP_CAGE_0
R156 R157 R201-R228 R231-R234 R460 R474 = RESISTOR_0: COMPHEIGHT: 0.000; DECOUPLER: NO; MEMORY: NO; PRECISION: 5%
U29 = XC17256L_11
X1 = XC17256L_12
J6 J7 = HEADER_6x2_SM_16: COMPHEIGHT: 0.000; DECOUPLER: NO; MEMORY: NO
P1 P2 = XC17256L_25
Q7 Q8 = XC17256L_7
U44 U45 = XC17256L_8
U32 = XC17256L_24
U33 U48 = XC17256L_22
DS4 DS5 DS7-DS11 = LED_1
SMATP16 = HEADER_6x2_SM_25: COMPHEIGHT: 0.000; DECOUPLER: NO; MEMORY: NO
SW2-SW5 = SW_PUSHBUTTON-SPST-2: COMPHEIGHT: 0.000; DECOUPLER: NO; MEMORY: NO
u46 u47 = SN74LVC244A_SO_18: COMPHEIGHT: 0.000; DECOUPLER: NO; MEMORY: NO
U71 = SN74LVC244A_SO_17: COMPHEIGHT: 0.000; DECOUPLER: NO; MEMORY: NO

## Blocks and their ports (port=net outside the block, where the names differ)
ADCREG = schematic ADC_ANALOG_REGULATORS, on sheet PAGE1: SYNTH_PWR=N9962816
FPGA13 = schematic FPGAZDOK, on sheet PAGE1: TX_DISABLE0=N9912646, TX_DISABLE1=N9913062, SCLK0P=SCLKP0, SCLK0N=SCLKN0, SCLK1P=SCLKP1, SCLK1N=SCLKN1, SCLK2P=SCLKP2, SCLK2N=SCLKN2, SYNTH_PWR=N9962816, PWRGD5V=N9963272, PMBUS_CLK=N9967323, PMBUS_CTRL=N9967512, PMBUS_DATA=N9967310, PMBUS_ALERT=N9967336, JTAG_TCLK=N9968007, JTAG_TDO=N9967995, JTAG_TDI=N9967983, JTAG_TMS=N9967965, FLASH_D[3:0], FPGA_FCS, FPGA_PROG_B=N9912452, DONE33V=N10001808, SM_FAN_PWM=N9998463, SCLK[2:0], SFP_STAT[5:0]
FPGA7 = schematic FPGAPOWER, on sheet PAGE1: no ports
BOARDLAYOUT = schematic BOARDLAYOUT, on sheet PAGE1: no ports
REG1 = schematic ANALOG_REGULATOR, on sheet PAGE1: PWRGD5V=N9963272
FPGA116 = schematic FPGASFPP, on sheet PAGE1: TX_DISABLE0=N9912646, TX_DISABLE1=N9913062, FPGA_DONE=N9997340, DONE33V=N10001808, SFP_STAT[5:0]
FPGA116/SFP2 = schematic SFPCONN, on sheet PAGE1: SFP_TX_DISABLE=N9913062, SFP_RX_N=FPGA116/N9876521, SFP_RX_P=FPGA116/N9876491, SFP_TX_N=FPGA116/N9876483, SFP_TX_P=FPGA116/N9876479, IIC_SCL_MAIN=FPGA116/N9876803, IIC_SDA_MAIN=FPGA116/N9876799, SFP_LOS=SFP_STAT5, SFP_TXF=SFP_STAT3, SFP_MD=SFP_STAT4
FPGA116/SWITCHES = schematic SWITCHES, on sheet PAGE1: SW0=FPGA116/N9971478, SW1=FPGA116/N9971482, SW2=FPGA116/N9971486, SW3=FPGA116/N9971490, LED0=FPGA116/N9971494, LED1=FPGA116/N9971498, LED2=FPGA116/N9971502, LED3=FPGA116/N9971506, LED4=FPGA116/N9971510, LED5=FPGA116/N9971514, OUT1PPS=FPGA116/N9971522, FPGA_DONE=N9997340, DONE33V=N10001808
FPGA116/SFP1 = schematic SFPCONN, on sheet PAGE1: SFP_TX_DISABLE=N9912646, SFP_RX_N=FPGA116/N9988522, SFP_RX_P=FPGA116/N9988534, SFP_TX_N=FPGA116/N9988648, SFP_TX_P=FPGA116/N9988636, IIC_SCL_MAIN=FPGA116/N9871999, IIC_SDA_MAIN=FPGA116/N9871987, SFP_LOS=SFP_STAT2, SFP_TXF=SFP_STAT0, SFP_MD=SFP_STAT1
FPGA116/OSCILLATORS = schematic OSCILLATORS, on sheet PAGE1: SYSCLK_N=FPGA116/CLK200MHZ_N, SYSCLK_P=FPGA116/CLK200MHZ_P, ETHCLK_N=FPGA116/ETHCLK_N, ETHCLK_P=FPGA116/ETHCLK_P, ETHCLK2_N=FPGA116/ETHCLK2_N, ETHCLK2_P=FPGA116/ETHCLK2_P
FPGA0 = schematic FPGAJTAG, on sheet PAGE1: CCLK=N9912822, QSPI_IC_CS_B=N9912826, FPGA_FCS, JTAG_TCLK=N9968007, JTAG_TDO=N9967995, FPGA_PROG_B=N9912452, JTAG_TDI=N9967983, JTAG_TMS=N9967965, FPGA_DONE=N9997340
FPGA32 = schematic FPGAADCS, on sheet PAGE1: SCLK0P=SCLKP0, SCLK0N=SCLKN0, SCLK1P=SCLKP1, SCLK1N=SCLKN1, SCLK2P=SCLKP2, SCLK2N=SCLKN2, PMBUS_CLK=N9967323, PMBUS_DATA=N9967310, PMBUS_ALERT=N9967336, SCLK[2:0]
FPGA14 = schematic QSPIFPGA, on sheet PAGE1: CCLK=N9912822, QSPI_IC_CS_B=N9912826, FLASH_D[3:0], FPGA_PROG_B=N9912452
POWER1 = schematic DIGITAL_POWER_SUPPLIES, on sheet PAGE1: PMBUS_CLK=N9967323, PMBUS_CTRL=N9967512, PMBUS_DATA=N9967310, PMBUS_ALERT=N9967336, SM_FAN_PWM=N9998463

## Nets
FPGA32/ADC1/VDDA1: C62.1 C63.1 C64.1 C65.1 C66.1 C68.1 C69.1 C70.1 L3.2 U7.1(AVDDa) U7.32(AVDD2) U7.36(AVDDb)
FPGA32/ADC1/VDDD: C73.1 C74.1 C75.1 C77.1 C78.1 L4.2 R423.1 R424.1 U7.7(DVDDb) U7.30(DVDDa) U7.33(OVDD)
FPGA116/SFP1/V3V3SFPR: C313.1 C314.1 L24.2 P1.15(VCCR)
FPGA116/SFP1/V3V3SFPT: C315.1 C316.1 L25.2 P1.16(VCCT)
FPGA116/SFP1/VCC3V3_IIC: C317.1 R209.2 U44.7(VREF2) U44.8(EN)
FPGA116/SFP2/V3V3SFPR: C319.1 C320.1 L26.2 P2.15(VCCR)
FPGA116/SFP2/V3V3SFPT: C321.1 C322.1 L27.2 P2.16(VCCT)
FPGA116/SFP2/VCC3V3_IIC: C323.1 R220.2 U45.7(VREF2) U45.8(EN)
FPGA116/VBUS: C220.1 C221.1 L14.2 U29.7(REGIN) U29.8(VBUS)
FPGA116/VBUS_USB: C216.1 J4.1(VBUS) J10.1(VBUS) L14.1 X1.2(CATH1)
GND: C43.2 C44.2 C46.2 C47.2 C51.2 C52.2 C57.2 C58.2 C60.2 C61.2 C62.2 C63.2 C64.2 C65.2 C66.2 C67.2 C68.2 C69.2 C70.2 C71.2 C72.2 C73.2 C74.2 C75.2 C76.2 C77.2 C78.2 C141.2 C142.2 C143.2 C144.2 C145.2 C146.2 C147.2 C148.2 C197.2 C198.2 C199.2 C200.2 C201.2 C202.2 C203.2 C204.2 C205.2 C206.2 C207.2 C208.2 C209.2 C210.2 C211.2 C212.2 C213.2 C214.2 C215.2 C217.2 C218.2 C219.2 C220.2 C221.2 C223.2 C226.2 C313.2 C314.2 C315.2 C316.2 C317.2 C318.2 C319.2 C320.2 C321.2 C322.2 C323.2 C324.2 C325.2 C326.2 C327.2 C328.2 C400.2 C401.2 C402.2 C403.2 C404.2 C405.2 C406.2 C407.2 C408.2 C409.2 C410.2 C411.2 C412.2 C413.2 C414.2 C415.2 C416.2 C417.2 C418.2 C419.2 C420.2 C591.2 C601.2 C602.2 J6.5 J6.6 J6.8 J7.5 J7.6 J7.8 L13.2 M23.1(G1) M23.2(G2) M23.3(G3) M23.4(G4) M23.5(G5) M23.6(G6) M23.7(G7) M23.8(G8) M23.9(G9) M23.10(G10) M23.11(G11) M23.12(G12) M23.13(G13) M23.14(G14) M23.15(G15) M23.16(G16) M23.17(G17) M23.18(G18) M23.19(G19) P1.1(VEET) P1.10(VEER_1) P1.11(VEER_2) P1.14(VEER_3) P1.17(VEET_2) P1.20(VEET_3) P2.1(VEET) P2.10(VEER_1) P2.11(VEER_2) P2.14(VEER_3) P2.17(VEET_2) P2.20(VEET_3) Q7.S(SOURCE) Q8.S(SOURCE) R38.1 R69.2 R70.1 R71.1 R223.2 R224.2 R225.2 R226.2 R227.2 R228.2 R230.2 R231.2 R232.2 R233.2 R234.2 R425.2 R440.1 SMATP16.2 SMATP16.3 T5.4 T6.6 T7.4 T8.6 U6.1(GND1) U6.2(GND2) U7.8(DVSSb) U7.29(DVSSa) U7.31(AVSS2) U7.39(AVSSa) U7.42(AVSSc) U7.45(AVSSb) U7.G0(AVSSd) U8.1(GND1) U8.2(GND2) U9.1(GND1) U9.2(GND2) U10.1(GND1) U10.2(GND2) U19.2(GND) U20.2(AGND1) U20.20(PGND1) U20.21(PGND2) U20.23(AGND2) U20.29(STSEL) U20.31(PGND3) U20.32(PGND4) U20.33(PGND5) U25.A1(GND) U25.A2(GND) U25.A5(GND) U25.A6(GND) U25.A7(GND) U25.A16(GND) U25.A26(GND) U25.AA6(GND) U25.AA16(GND) U25.AA26(GND) U25.AB3(GND) U25.AB13(GND) U25.AB23(GND) U25.AC10(GND) U25.AC20(GND) U25.AD7(GND) U25.AD17(GND) U25.AE4(GND) U25.AE14(GND) U25.AE24(GND) U25.AF1(GND) U25.AF11(GND) U25.AF21(GND) U25.B4(GND) U25.B5(MGTXRXN3_116) U25.B6(MGTXRXP3_116) U25.B7(GND) U25.B13(GND) U25.B23(GND) U25.C1(GND) U25.C3(MGTXRXN2_116) U25.C4(MGTXRXP2_116) U25.C5(GND) U25.C7(GND) U25.C10(GND) U25.C20(GND) U25.D4(GND) U25.D7(GND) U25.D17(GND) U25.E1(GND) U25.E2(GND) U25.E3(MGTXRXN1_116) U25.E4(MGTXRXP1_116) U25.E5(GND) U25.E7(GND) U25.E14(GND) U25.E24(GND) U25.F3(GND) U25.F4(GND) U25.F7(GND) U25.F11(GND) U25.F21(GND) U25.G1(GND) U25.G3(MGTXRXN0_116) U25.G4(MGTXRXP0_116) U25.G5(GND) U25.G8(GND) U25.G18(GND) U25.H4(GND) U25.H7(GND) U25.H15(GND) U25.H25(GND) U25.J1(GND) U25.J2(GND) U25.J3(MGTXRXN3_115) U25.J4(MGTXRXP3_115) U25.J5(GND) U25.J12(GND) U25.J22(GND) U25.K3(GND) U25.K4(GND) U25.K7(GND) U25.K9(GND) U25.K11(GND) U25.K13(GND) U25.K19(GND) U25.L1(GND) U25.L5(GND) U25.L10(GND) U25.L12(GND) U25.L14(GND) U25.L16(GND) U25.L26(GND) U25.M4(GND) U25.M7(GND) U25.M9(GND) U25.M13(GND) U25.M15(GND) U25.M23(GND) U25.N1(GND) U25.N2(GND) U25.N3(MGTXRXN1_115) U25.N4(MGTXRXP1_115) U25.N5(GND) U25.N7(GND) U25.N10(GND) U25.N14(GND) U25.N20(GND) U25.P3(GND) U25.P4(GND) U25.P9(GND) U25.P13(GND) U25.P15(GND) U25.P17(GND) U25.R1(GND) U25.R2(GND) U25.R5(GND) U25.R8(GND) U25.R10(GND) U25.R14(GND) U25.R24(GND) U25.T1(GND) U25.T3(GND) U25.T4(GND) U25.T9(GND) U25.T11(GND) U25.T13(GND) U25.T15(GND) U25.T21(GND) U25.U8(GND) U25.U10(GND) U25.U12(GND) U25.U14(GND) U25.U18(GND) U25.V5(GND) U25.V15(GND) U25.V25(GND) U25.W2(GND) U25.W12(GND) U25.W22(GND) U25.Y9(GND) U25.Y19(GND) U29.2(GND) U29.29(CNR_GND) U29.30(CTR_GND) U32.3(GND1) U32.7(GND2) U33.3(GND) U44.1(GND) U45.1(GND) u46.1(1~{OE}) u46.10(GNDA) u46.11(GNDB) u46.16(2~{OE}) u47.1(1~{OE}) u47.10(GNDA) u47.11(GNDB) u47.16(2~{OE}) U48.3(GND) U71.2(DIR) U71.11(GND1) U71.12(GND2) U71.13(GND3) U71.22(~{OE}) ; also on sheet 2 3 4 5 15 16 17 18 19 20 21 22 23 24 25 26 27
VCC1V8_ADC: C60.1 C61.1 C71.1 C72.1 C199.1 C200.1 C202.1 L3.1 L4.1 R37.2 U25.AA1(VCCO_34) U25.AA11(VCCO_33) U25.AB8(VCCO_33) U25.AB18(VCCO_32) U25.AC5(VCCO_34) U25.AC15(VCCO_32) U25.AD2(VCCO_34) U25.AD12(VCCO_33) U25.AE9(VCCO_33) U25.AE19(VCCO_32) U25.AF6(VCCO_34) U25.AF16(VCCO_32) U25.U3(VCCO_34) U25.V10(VCCO_33) U25.W7(VCCO_33) U25.W17(VCCO_32) U25.Y4(VCCO_34) U25.Y14(VCCO_32) ; also on sheet 3 4 5 23
VCC3V3: C205.1 C226.1 C326.1 C328.1 C591.1 C601.1 L24.1 L25.1 L26.1 L27.1 R201.1 R202.1 R203.1 R204.1 R205.1 R206.1 R207.1 R208.1 R209.1 R212.1 R213.1 R214.1 R215.1 R216.1 R217.1 R218.1 R219.1 R220.1 U25.B18(VCCO_15) U25.E19(VCCO_15) U25.F16(VCCO_15) U25.H20(VCCO_15) U25.J17(VCCO_15) U25.M18(VCCO_15) U33.1(OE) U33.6(VCC) u46.2(VCCB) u47.2(VCCB) U48.1(OE) U48.6(VCC) U71.24(VCCB) ; also on sheet 2 15 22 27
VCC5V0: C141.1 C146.1 C147.1 C602.1 R443.1 U19.1(VIN) U19.3(EN) U20.34(VOUT1) U20.35(VOUT2) U20.36(VOUT3) U20.37(VOUT4) U20.38(VOUT5) U20.41(VOUT6) U71.1(VCCA) ; also on sheet 23 25 27
VCC12_P: C143.1 C144.1 C145.1 C148.1 U20.1(PVIN1) U20.3(VIN) U20.11(PVIN2) U20.12(PVIN3) U20.39(PVIN4) U20.40(PVIN5) ; also on sheet 15 16 17 18 19 20 21 22
VCC_SPI: C142.1 R68.1 U19.5(VOUT) ; also on sheet 24
VCCAUX: C212.1 C213.1 C214.1 U25.L11(VCCAUX) U25.M10(VCCAUX) U25.P8(VCCAUX_IO_G0) U25.P10(VCCAUX) U25.R9(VCCAUX_IO_G0) U25.T8(VCCAUX_IO_G0) U25.T10(VCCAUX) U25.U11(VCCAUX) ; also on sheet 15 22 27
VCCAUXMGT: U25.N6(MGTVCCAUX) ; also on sheet 15 19
VCCBRAM: C208.1 C209.1 C210.1 C211.1 C413.1 C414.1 C415.1 C416.1 C417.1 C418.1 C419.1 C420.1 U25.N13(VCCBRAM) U25.R13(VCCBRAM) U25.T12(VCCBRAM) U25.U13(VCCBRAM) ; also on sheet 15 18
VCCINT: C206.1 C207.1 C400.1 C401.1 C402.1 C403.1 C404.1 C405.1 C406.1 C407.1 C408.1 C409.1 C410.1 C411.1 C412.1 U25.J9(VCCINT) U25.K8(VCCINT) U25.K10(VCCINT) U25.K12(VCCINT) U25.K14(VCCINT) U25.L9(VCCINT) U25.L13(VCCINT) U25.L15(VCCINT) U25.M8(VCCINT) U25.M14(VCCINT) U25.N9(VCCINT) U25.N15(VCCINT) U25.P14(VCCINT) U25.R15(VCCINT) U25.T14(VCCINT) U25.U15(VCCINT) ; also on sheet 15 17
VCCMGTA: R156.1 U25.C6(MGTAVCC) U25.E6(MGTAVCC) U25.G6(MGTAVCC) U25.J6(MGTAVCC) U25.L6(MGTAVCC) U25.M5(MGTAVTTRCAL_115) ; also on sheet 15 16
FPGA32/ADC1/VCM: C43.1 C44.1 C46.1 C47.1 C51.1 C52.1 C57.1 C58.1 R22.2 R23.1 R24.2 R27.1 R30.2 R31.1 R34.2 R35.1 U7.48(VCM)
FPGA32/ADC1_OUT0: U7.9(DP1A) ; also on sheet 3
FPGA32/ADC1_OUT1: U7.10(DN1A) ; also on sheet 3
FPGA32/ADC1_OUT2: U7.11(DP1B) ; also on sheet 3
FPGA32/ADC1_OUT3: U7.12(DN1B) ; also on sheet 3
FPGA32/ADC1_OUT4: U7.13(DP2A) ; also on sheet 3
FPGA32/ADC1_OUT5: U7.14(DN2A) ; also on sheet 3
FPGA32/ADC1_OUT6: U7.15(DP2B) ; also on sheet 3
FPGA32/ADC1_OUT7: U7.16(DN2B) ; also on sheet 3
FPGA32/ADC1_OUT8: U7.21(DP3A) ; also on sheet 3
FPGA32/ADC1_OUT9: U7.22(DN3A) ; also on sheet 3
FPGA32/ADC1_OUT10: U7.23(DP3B) ; also on sheet 3
FPGA32/ADC1_OUT11: U7.24(DN3B) ; also on sheet 3
FPGA32/ADC1_OUT12: U7.25(DP4A) ; also on sheet 3
FPGA32/ADC1_OUT13: U7.26(DN4A) ; also on sheet 3
FPGA32/ADC1_OUT14: U7.27(DP4B) ; also on sheet 3
FPGA32/ADC1_OUT15: U7.28(DN4B) ; also on sheet 3
FPGA32/ADCSMA4: U6.4(I1) ; also on sheet 3
FPGA32/ADCSMA5: U8.3(I2) ; also on sheet 3
FPGA32/ADCSMA6: U9.4(I1) ; also on sheet 3
FPGA32/ADCSMA7: U10.3(I2) ; also on sheet 3
FPGA32/CSN1: U7.2(CSN) ; also on sheet 3
FPGA32/FCLKN1: U7.20(FCLKN) ; also on sheet 3
FPGA32/FCLKP1: U7.19(FCLKP) ; also on sheet 3
FPGA32/LCLKN1: U7.18(LCLKN) ; also on sheet 3
FPGA32/LCLKP1: U7.17(LCLKP) ; also on sheet 3
FPGA32/PD1: R423.2 R425.1 U7.6(PD) ; also on sheet 3
FPGA32/RSTN1: R424.2 U7.5(RSTN) ; also on sheet 3
FPGA32/SDATA1: U7.3(SDATA) ; also on sheet 3
FPGA116/CLK200MHZ_N: U25.D10(IO_L12N_T1_MRCC_16) U32.5(OUT_B)
FPGA116/CLK200MHZ_P: U25.E10(IO_L12P_T1_MRCC_16) U32.4(OUT)
FPGA116/ETHCLK2_N: C593.2 U25.H5(MGTREFCLK0N_115)
FPGA116/ETHCLK2_P: C592.2 U25.H6(MGTREFCLK0P_115)
FPGA116/ETHCLK_N: C224.2 U25.K5(MGTREFCLK1N_115)
FPGA116/ETHCLK_P: C225.2 U25.K6(MGTREFCLK1P_115)
FPGA116/OSCILLATORS/ETHCLK: C225.1 U33.4(OUT)
FPGA116/OSCILLATORS/ETHCLK2: C592.1 U48.4(OUT)
FPGA116/OSCILLATORS/ETHCLK2_B: C593.1 U48.5(OUT_B)
FPGA116/OSCILLATORS/ETHCLK_B: C224.1 U33.5(OUT_B)
FPGA116/SFP1/SFP_IIC_SCL: P1.5(SCL) R205.2 U44.6(SCL2)
FPGA116/SFP1/SFP_IIC_SDA: P1.4(SDA) R206.2 U44.5(SDA2)
FPGA116/SFP1/SFP_RS0: J6.3 P1.7(RS0)
FPGA116/SFP1/SFP_RS1: J6.4 P1.9(RS1)
FPGA116/SFP1/SFP_TX_DISABLE_TRANS: J6.7 P1.3(TX_DISABLE) Q7.D(DRAIN) R202.2
FPGA116/SFP2/SFP_IIC_SCL: P2.5(SCL) R216.2 U45.6(SCL2)
FPGA116/SFP2/SFP_IIC_SDA: P2.4(SDA) R217.2 U45.5(SDA2)
FPGA116/SFP2/SFP_RS0: J7.3 P2.7(RS0)
FPGA116/SFP2/SFP_RS1: J7.4 P2.9(RS1)
FPGA116/SFP2/SFP_TX_DISABLE_TRANS: J7.7 P2.3(TX_DISABLE) Q8.D(DRAIN) R213.2
FPGA116/SWITCHES/GPIO_LED_0: DS8.A(ANODE) u47.15(1B1)
FPGA116/SWITCHES/GPIO_LED_1: DS9.A(ANODE) u47.14(1B2)
FPGA116/SWITCHES/GPIO_LED_2: DS10.A(ANODE) u47.13(2B1)
FPGA116/SWITCHES/GPIO_LED_3: DS11.A(ANODE) u47.12(2B2)
FPGA116/SWITCHES/GPIO_LED_4: DS4.A(ANODE) u46.15(1B1)
FPGA116/SWITCHES/GPIO_LED_5: DS5.A(ANODE) u46.14(1B2)
FPGA116/SWITCHES/OUT1PPS5V: R474.2 U71.4(A2) U71.5(A3) U71.6(A4) U71.7(A5) U71.8(A6) U71.9(A7) U71.10(A8)
FPGA116/SWITCHES/OUT1PPS33V: u46.12(2B2) U71.14(B8) U71.15(B7) U71.16(B6) U71.17(B5) U71.18(B4) U71.19(B3) U71.20(B2) U71.21(B1)
FPGA116/USB_CTS: U25.F10(IO_L11N_T1_SRCC_16) U29.22(CTS)
FPGA116/USB_D_N: J4.2(D_N) J10.2(D_N) U29.4(D-) X1.3(CATH2)
FPGA116/USB_D_P: J4.3(D_P) J10.3(D_P) U29.3(D+) X1.4(CATH3)
FPGA116/USB_GND: C216.2 J4.5(GND) J10.5(GND) L13.1
FPGA116/USB_RTS: U25.J13(IO_L3P_T0_DQS_16) U29.23(RTS)
FPGA116/USB_RX: U25.H13(IO_L3N_T0_DQS_16) U29.24(RXD)
FPGA116/USB_SHIELD: C215.1 J10.6(SHLD1) J10.7(SHLD2) J10.8(SHLD3) R460.1 X1.1(ANODES)
FPGA116/USB_TX: U25.J8(IO_0_16) U29.25(TXD)
REG1/SENSE_5V0: R443.2 U20.27(SENSE+)
REG1/SENSE_SPI: R68.2 R69.1 U19.4(ADJ)
REG1/VPH: U20.10(PH1) U20.13(PH2) U20.14(PH3) U20.15(PH4) U20.16(PH5) U20.17(PH6) U20.18(PH7) U20.19(PH8) U20.42(PH9)
SCLK1: R440.2 U7.4(SCLK) ; also on sheet 25
SCLKN1: R40.2 U7.34(CLKN) ; also on sheet 26
SCLKP1: R39.1 U7.35(CLKP) ; also on sheet 26
SFP_STAT0: J6.9 P1.2(TX_FAULT) R201.2 ; also on sheet 25
SFP_STAT1: J6.11 P1.6(MOD_ABS) R203.2 ; also on sheet 25
SFP_STAT2: J6.10 P1.8(LOS) R204.2 ; also on sheet 25
SFP_STAT3: J7.9 P2.2(TX_FAULT) R212.2 ; also on sheet 25
SFP_STAT4: J7.11 P2.6(MOD_ABS) R214.2 ; also on sheet 25
SFP_STAT5: J7.10 P2.8(LOS) R215.2 ; also on sheet 25
VADJ: C197.1 C198.1 C201.1 C203.1 C204.1 C217.1 C218.1 C223.1 C318.1 C324.1 C325.1 C327.1 R157.1 R210.1 R211.1 R221.1 R222.1 SW2.4 SW3.4 SW4.4 SW5.4 U25.A11(VCCO_16) U25.A21(VCCO_14) U25.AA21(VCCO_12) U25.AC25(VCCO_12) U25.AD22(VCCO_12) U25.AF26(VCCO_12) U25.B8(VCCO_16) U25.C15(VCCO_16) U25.C25(VCCO_14) U25.D12(VCCO_16) U25.D22(VCCO_14) U25.E9(VCCO_16) U25.F26(VCCO_14) U25.G13(VCCO_16) U25.G23(VCCO_14) U25.H10(VCCO_16) U25.K24(VCCO_13) U25.L7(VCCO_0) U25.L21(VCCO_14) U25.N25(VCCO_13) U25.P22(VCCO_13) U25.R19(VCCO_13) U25.T6(VCCO_0) U25.T16(VCCO_13) U25.T26(VCCO_13) U25.U23(VCCO_12) U25.V20(VCCO_12) U25.Y24(VCCO_12) U29.5(VIO) U32.1(OE) U32.6(VCC) U44.2(VREF1) U45.2(VREF1) u46.3(VCCA) u46.4(1DIR) u46.5(2DIR) u47.3(VCCA) u47.4(1DIR) u47.5(2DIR) ; also on sheet 2 15 18 23 24 25 27
VTTMGTA: U25.B3(MGTAVTT) U25.C2(MGTAVTT) U25.D3(MGTAVTT) U25.G2(MGTAVTT) U25.H3(MGTAVTT) U25.L2(MGTAVTT) U25.M3(MGTAVTT) ; also on sheet 15 16
FPGA32/ADC1/N168454: C67.1 C76.1 R37.1 R38.2 R39.2 R40.1
FPGA32/ADC1/N168582: C56.2 R35.2 R36.2 U7.37(IN4)
FPGA32/ADC1/N168590: C56.1 R33.2 R34.1 U7.38(IP4)
FPGA32/ADC1/N168598: C53.2 R31.2 R32.2 U7.40(IN3)
FPGA32/ADC1/N168606: C53.1 R29.2 R30.1 U7.41(IP3)
FPGA32/ADC1/N168618: C48.2 R27.2 R28.2 U7.43(IN2)
FPGA32/ADC1/N168630: C48.1 R24.1 R26.2 U7.44(IP2)
FPGA32/ADC1/N168650: C41.2 R23.2 R25.2 U7.46(IN1)
FPGA32/ADC1/N168658: C41.1 R21.2 R22.1 U7.47(IP1)
FPGA32/ADC1/N168814: T5.6 U6.3(I2)
FPGA32/ADC1/N168842: T6.4 U8.4(I1)
FPGA32/ADC1/N168902: T7.6 U9.3(I2)
FPGA32/ADC1/N169034: T8.4 U10.4(I1)
FPGA32/ADC1/N169678: C40.1 T5.1
FPGA32/ADC1/N169712: C42.1 T5.3
FPGA32/ADC1/N169780: C40.2 R21.1
FPGA32/ADC1/N169792: C42.2 R25.1
FPGA32/ADC1/N169940: C45.1 T6.3
FPGA32/ADC1/N169968: C49.1 T6.1
FPGA32/ADC1/N170050: C45.2 R26.1
FPGA32/ADC1/N170062: C49.2 R28.1
FPGA32/ADC1/N170286: C50.2 R29.1
FPGA32/ADC1/N170298: C54.2 R32.1
FPGA32/ADC1/N170430: C50.1 T7.1
FPGA32/ADC1/N170484: C54.1 T7.3
FPGA32/ADC1/N170586: C55.2 R33.1
FPGA32/ADC1/N170598: C59.2 R36.1
FPGA32/ADC1/N170658: C55.1 T8.3
FPGA32/ADC1/N170734: C59.1 T8.1
FPGA116/N9871987: R210.2 U25.J10(IO_L4N_T0_16) U44.4(SDA1)
FPGA116/N9871999: R211.2 U25.J11(IO_L4P_T0_16) U44.3(SCL1)
FPGA116/N9876479: P2.18(TD_P) U25.K2(MGTXTXP2_115)
FPGA116/N9876483: P2.19(TD_N) U25.K1(MGTXTXN2_115)
FPGA116/N9876491: P2.13(RD_P) U25.L4(MGTXRXP2_115)
FPGA116/N9876521: P2.12(RD_N) U25.L3(MGTXRXN2_115)
FPGA116/N9876799: R221.2 U25.G9(IO_L2N_T0_16) U45.4(SDA1)
FPGA116/N9876803: R222.2 U25.G10(IO_L2P_T0_16) U45.3(SCL1)
FPGA116/N9878353: C219.1 U29.6(VDD)
FPGA116/N9878369: R157.2 U29.9(RST_B)
FPGA116/N9971478: R223.1 SW2.2(1) U25.F13(IO_L15N_T2_DQS_16)
FPGA116/N9971482: R226.1 SW4.2(1) U25.F14(IO_L15P_T2_DQS_16)
FPGA116/N9971486: R224.1 SW3.2(1) U25.F12(IO_L16N_T2_16)
FPGA116/N9971490: R227.1 SW5.2(1) U25.G12(IO_L16P_T2_16)
FPGA116/N9971494: U25.D13(IO_L17N_T2_16) u47.6(1A1)
FPGA116/N9971498: U25.D14(IO_L17P_T2_16) u47.7(1A2)
FPGA116/N9971502: U25.E12(IO_L18N_T2_16) u47.8(2A1)
FPGA116/N9971506: U25.E13(IO_L18P_T2_16) u47.9(2A2)
FPGA116/N9971510: U25.C13(IO_L19N_T3_VREF_16) u46.6(1A1)
FPGA116/N9971514: U25.C14(IO_L19P_T3_16) u46.7(1A2)
FPGA116/N9971522: U25.H9(IO_L1P_T0_16) u46.9(2A2)
FPGA116/N9988387: R156.2 U25.M6(MGTRREF_115)
FPGA116/N9988522: P1.12(RD_N) U25.R3(MGTXRXN0_115)
FPGA116/N9988534: P1.13(RD_P) U25.R4(MGTXRXP0_115)
FPGA116/N9988636: P1.18(TD_P) U25.P2(MGTXTXP0_115)
FPGA116/N9988648: P1.19(TD_N) U25.P1(MGTXTXN0_115)
FPGA116/N10001570: J4.6(SHLD1) J4.7(SHLD2) J4.8(SHLD3) J4.9(SHLD9) R460.2
FPGA116/SFP1/N9876614: J6.2 R208.2
FPGA116/SFP1/N9876618: J6.1 R207.2
FPGA116/SFP2/N9876614: J7.2 R219.2
FPGA116/SFP2/N9876618: J7.1 R218.2
FPGA116/SWITCHES/N9968678: DS8.C(CATHODE) R231.1
FPGA116/SWITCHES/N9968738: DS9.C(CATHODE) R232.1
FPGA116/SWITCHES/N9968766: DS10.C(CATHODE) R233.1
FPGA116/SWITCHES/N9968778: DS11.C(CATHODE) R234.1
FPGA116/SWITCHES/N9969082: DS4.C(CATHODE) R225.1
FPGA116/SWITCHES/N9969110: DS5.C(CATHODE) R228.1
FPGA116/SWITCHES/N9969130: DS7.A(ANODE) U71.3(A1)
FPGA116/SWITCHES/N9969134: DS7.C(CATHODE) R230.1
FPGA116/SWITCHES/N9992884: R474.1 SMATP16.1
N9912646: Q7.G(GATE) ; also on sheet 25
N9913062: Q8.G(GATE) ; also on sheet 25
N9963272: U20.8(PWRGD) ; also on sheet 25
N9997340: u46.8(2A1) ; also on sheet 2
N10001808: u46.13(2B1) ; also on sheet 25
REG1/N10011441: R70.2 U20.22(RT/CLK)
REG1/N10011683: R71.2 U20.26(VADJ)

Not connected (* = marked no-connect by the designer): J4 4(ID)*; J6 12*; J7 12*; J10 4(ID)*; SW2 1(3) 3(2); SW3 1(3) 3(2); SW4 1(3) 3(2); SW5 1(3) 3(2); T5 2*; T6 2*; T7 2*; T8 2*; U20 4(OCP_SEL)* 5(DNC1)* 6(ILIM)* 7(SYNC_OUT)* 9(DNC2)* 24(DNC3)* 25(ISHARE)* 28(SS/TR)* 30(INH/UVLO)*; U25 A3(MGTXTXN3_116) A4(MGTXTXP3_116) A8(IO_L9N_T1_DQS_16) A9(IO_L9P_T1_DQS_16) A10(IO_L22N_T3_16) A12(IO_L24N_T3_16) A13(IO_L24P_T3_16) A14(IO_L21N_T3_DQS_16) A15(IO_L23N_T3_16) B1(MGTXTXN2_116) B2(MGTXTXP2_116) B9(IO_L10N_T1_16) B10(IO_L22P_T3_16) B11(IO_L20N_T3_16) B12(IO_L20P_T3_16) B14(IO_L21P_T3_DQS_16) B15(IO_L23P_T3_16) C9(IO_L10P_T1_16) C11(IO_L13N_T2_MRCC_16) C12(IO_L13P_T2_MRCC_16) D1(MGTXTXN1_116) D2(MGTXTXP1_116) D5(MGTREFCLK0N_116) D6(MGTREFCLK0P_116) D8(IO_L8N_T1_16) D9(IO_L8P_T1_16) D11(IO_L14N_T2_SRCC_16) E11(IO_L14P_T2_SRCC_16) F1(MGTXTXN0_116) F2(MGTXTXP0_116) F5(MGTREFCLK1N_116) F6(MGTREFCLK1P_116) F8(IO_L7N_T1_16) F9(IO_L7P_T1_16) G11(IO_L11P_T1_SRCC_16) G14(IO_L5N_T0_16) H1(MGTXTXN3_115) H2(MGTXTXP3_115) H8(IO_L1N_T0_16) H11(IO_L6N_T0_VREF_16) H12(IO_L6P_T0_16) H14(IO_L5P_T0_16) J14(IO_25_16) M1(MGTXTXN1_115) M2(MGTXTXP1_115); U29 1(RI)* 10(NC1)* 11(SUSPEND_B)* 12(SUSPEND)* 13(NC2)* 14(NC3)* 15(NC4)* 16(GPIO3)* 17(GPIO2)* 18(GPIO1)* 19(GPIO0)* 20(NC5)* 21(NC6)* 26(DSR)* 27(DTR)* 28(DCD)*; U32 2(NC)*; U33 2(NC)*; U48 2(NC)*; U71 23(NC)*

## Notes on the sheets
sheet 6
- Note 1:  Components associated with ADC inputs IP1 and IP3 are on the top side of the board.
           Components associated with IP2 and IP4 are on the bottom side of the board.
- From Xilinx, 1.8-volt logic
- Note 2: Layout the board such that the attenuators can be replaced by 0402 zero ohm jumpers.
- Maximum Digital
  Input Voltage of
  3.9V
- Note 2
- Digikey 1127-1648-ND
- Note 1
- LVDS to Xilinx
- From SMA connectors
- LVDS to Xilinx
- I = 435 ma (counting LVDS outptuts)
- From linear regulator LP3856
- pin 1
- From linear regulator LP3856
- pin 36
- rev 2014-2-4: Change 3db pad vendor.  Change analog terms.
- rev 2014-1-29: Add 3db pads to inputs for matching
- rev 2013-11-14: update to 5/28/2013 Berkeley version:
                  change xformer type and AC coupled xformer.
                  Also update to preferred values for input terminations
- rev 2014-1-3: fix typo in notes
- U1, pin 32
- rev 2013-10-23: Add to/from notes for I/O.
                  Change name and symbol for power
- rev 2013-10-27: Show ADC data outputs as bus to simplify high level view.
                  Eliminate 0.1 uF cap on CLK_IN_P/N
- rev 2014-5-14:  Add PU and PDs to PD and RSTN.
- From Clock Generator
  LVPECL input, capacitively coupled
- Change name of DVDD & OVDD to VDDO & VDDD
sheet 7
- Changes for Rev. C
- NOT Done yet
- See the Design Manual for a detailed explanation.
- F20
- E20
- C20
- B20
- Done
- D20
- A20
- Fix the footprint of the ZDOK connector so it doesn't have the offset pins.
- On the Xilinx silkscreen label pins from A1 to A26, not A1 to AF26.
- Make the probe points on the back of the Xilinx not covered with laquer.
- Add RFI cage for SFP+ with 19 grounded connections
- Add 22 2-56 mounting holes with electrical connections to ground
- Move J2 (the 12V source), so it does not conflict with U24.  Note that the wiring was reversed to do this.
- Change Voltage source of R61 from V5.0 to VADJ_FPGA to prevent an
  overvoltage to the Xilinx input, SH 5
- TOP VIEW
- 1
- After Changes
- 26
- Change Voltage source of R431 from VCC2V5 to VCC3V3 to prevent an
  overvoltage to the Xilinx input, SH 9
- GTX
- High Range
- High Range
- High Range
- Add a 125 MHz oscillator for 1 GbE, SH 15
- Modify JTAG connectors J3 & J11 pinout to industry standard, SH 11.
- A
- Move pin labels on the following resistor for clarity:
      R17, R18, R37, R38, R57, R58
- 116
- 16
- 15
- 14
- Pins 15-20
- SYNTHMUXOUT added to connect U21 Synthesizer MUXOUT to Xilinx, SH 8.
- SFP 1
- SFP CTRL
- Rasp PI
- ZDOK
- Added connections of SFP status lines to Xilinx, SH 24, 25
- 2.5V
- SYNTH CLKS
- 3.3V
- SPI
- Changes for Rev B
  (first manufacturing run)
- GTX
- High Range
- 2.5V
- 115
- 0
- GND
- 13
- SFP 2
- JTAG
- ZDOK
- Pins 7-14
- Change 33 to 1.8V and move ADC 1 to it.
- 2.5V
- 2.5V
- Move ZDOK to 16 to 14, SPI 14 to 15, and sfp ctrl to 15 to 16
- Use only MRCC clocks for the ADCs
- High
  Performance
- High
  Performance
- High
  Performance
- High Range
- CARD EDGE
- Redistribute ZDOK pins.
- Change ZDOK to 2.5V VCCO so can use LVDS-25 See UG471.
- Change 100MHZ OSC to 200 MHZ.  and eliminate termination resistor.
- 34
- 33
- 32
- 12
- Pins 1-6
- Replace 5V linear regulator with a DC-DC converter
- ADC 0
- ADC 1
- ADC 2
- ZDOK
- PI
- Reduce number of TI Power Supply Controllers from 3 to 2
- CLKS, LEDS
- 2.5V
- Add J9 as a test connector
- Remove C196 which wasn't connected to anything.
- AF
- 1.8V
- 1.8V
- 1.8V
- Go to a single dual SFP+ Cage instead of two single cages.
- Add a vertical USB J10 in parallel with horizontal USB J4
- XILINX
- Change U43 from a 128 MByte to a 256 MByte Flash Memory.
- Move the SPI pins to Bank 14 as on the Kintex Evaluation Board.
- Add DNP bypass capacitors to allow for larger Xilinxs
- Hook up the FPGA_DONE and FPGA_PROG_B pins to the PI header thru level shifters
- Move PI signals to Bank 15 with a VCCO of 3.3V.
- Move ZDOK clock lines to match the Roach II.
- Change BOM to give options for 3 Xilinxs.
- F1
- C1
- Add PU or PD to PD on the ADCs.
- E1
- B1
- Add Heatsink to BOM
- D1
- A1
- Add fan power receptacle with PWM
- Arrange ADC Out pin parings so similar lengths.
- ZDOK Pin Layout
- Moved CLK_SEL_B and CLK_SEL_A to bank 15 which has the needed VCCO of 3.3V.
- Install PD and DNP PU on PUDC_B pin.
- Remove LK_DET TP3, since there were two test points.
- Add net names V3V3SFPR, V3V3SFPT,V2V5ADC,V5V0DRV,V5V0SYN,V12PWRCTRL,V12D020W,V12D210W,V12D010W
- Have ADC SCLK signals from 3.3V Voltage divider to terminate.
- Move SYNTH_(CLK,DATA,LE,CE,BE) to 3.3V, then put series/parallel resistor on SYNTH_CLK.
- Change Footprint of DNP resistors R114,R133,R135,R139 so they match the placed resistors.
- Add zero Ohm resistors R442,R443 and make SENSE_... nets for sense lines.
- Fix Pinout of U28,U46, & U47 so it matchs the BOM part number which is SN74AVC4T245RSVR
- Fix typo to add VCC_3V3SYN to VCC3V3_SYN net.
- Remove U27 and its resistors.  Put in a 6pin vertical J3 and right angle jtag header J11.  Move Xilinx Temperature to JP4.
- Add a second ground pin to SMATP1 through 16.
- Add ground test points GNDTP1-5.
- Make Horizontal USB Connector J4 DNP so it won't short to the rail in a box.  Also add a 0 Ohm DNP jumper.
- Deleted U25-E26 from net C20, and deleted U25-F25 from net C19.
- To accomdate the new Pi B+, change PI2 from 26 to 40 pins & eliminate P8.
sheet 8
- 2.8V @ 300mA
- See KC705 sheet 46 Linear Power Supplies
- Powers SPI Flash that stores FPGA personality
- R1 1/16W 0.11%
- R2 1/16W 0.1%
- VOUT = 0.5 V(1 + R1/R2) + (0.000000015A)(R1)
- Change from 4.53K and 1K since did not give right voltage.
- VOUT = 2.8200V
- 5V @ 10A Switching Power Supply
- Powers Raspberry Pi, ADCs
- Pins 41 and 42 are large pads in the center of the chip
- Connect PH pins via a small copper island.
- There are many large electrolytic capacitors on
  12V at the DC-DC converters, so not included
  here.
- 1MHz optimal for
  12V to 5V
- Selects 5V
- Sinks low if output
  Voltage > 6% out of
  regulation.
sheet 9
- Probably set Vadj to 2.5V
- See KC705 Sheet 25
- 12 - 16 High Range
- VCCINT can be
  0.9 or 1.0 V
  to trade off
  speed and
  power.
- 32 - 34 High Precision
- See Sheet 12 of KC705
- HR I/O Bank has 3.465 VCCO max
- HP I/O Bank has 1.89 VCCO max
- VCCBRAM 330 uF: have 0 for 160T, 0 for 325T, 1 for 410T Xilinx
- VCCINT 4.7uF:  0 for 160T, 5 for 325T, 10 for 410T Xilinx
- See the SNAP board design guide for a discussion of the Kintex Decoupling Capacitors.
- VCCINT can be
  0.9 or 1.0 V
  to trade off
  speed and
  power.
- Per UG483, the xc7k160t ffg676requires the following bypass capacitors:
- See UG483 for layout guidlines
- VCCBRAM 100 uF: have 1 for 160T, 2 for 325T, 0 for 410T Xilinx
- VCCBRAM 4.7 uF: have 3 for 160T, 5 for 325T, 9 for 410T Xilinx
- VCCINT 330 uF: have 2 for 160T, 3 for 325T, 5 for 410T Xilinx
- T520V337M2R5ATE025
- GRM32ER60J107ME20L
- Digikey 399-4105-1-ND
- GRM155R60J475ME47D
- Per Group
  see UG471
  and UG475
- Bank 0
- GRM43ER61A476KE19L
sheet 10
- Leave Unused REFCLKs unconnected
- See Sheet 9 of the KC705
- VCCO is VCC2V5
- Contains P1 in Sheet 24
- Sheet 15
- HIGH RANGE
- See UG476 7 Series FPGAs GTX/GTH Tranceivers User Guide
- 10 GBE high speed traces require special layout care.
- Sheet 26
- See UG483 - 7 Series FPGAs PCB Design and Pin Planning Guide
- See Sheet 9 of the KC705
- Contains P2 in Sheet 25
- Group SFP status signals
  for convnience in ascending
  to next level of hierarchy
- To Bank 15 above
- Digikey 240-2399-2--ND
- HZ0805E601R-10
- Transient Surpressor
- Digikey F2715CT-ND
- TE Connectivity 1734753-1
- Digikey A107790-ND
- Molex 548190589 (horizontal)
- Digikey WM3895CT-ND
- See Sheet 27 of the KC705
- If desired for a card cage J4, a right angle USB
  can be installed in parallel.
- If used, also install a zero Ohm resistor for 1206 R460
- J4 is DNP if the card is in the box, since the shield pins
  would short out to the ground rail.
- HZ0805E601R-10
- Digikey 240-2399-2--ND
- Digikey 336-1164-ND
- USB BUS POWERED
sheet 11
- SFP Status Signals
- Digikey 541-1222-1-ND
- From Bank 12, KC705 Sheet 3
- Similar to Bank 117 on Sheet 9 of the KC705
- SFP+ Connector  Digikey WM1696CT-ND
- Now a dual cage is added at layout as a mechanical part.
- Digikey NDS331NCT-ND
- JUMPER
- JUMPER
- 1-3: FULL BW RX
- 2-4:  FULL BW TX
- Note Sheet 22 shows a pin 32 in error.
- 3-5: LOW BW RX
- 4-6:  LOW BW TX
- See Sheet 22 of the KC705
- 9:  SFP_TX_FAULT
- 10:  SFP_LOS
- 7-8:  SFP Enable
- 11:  SFP_MOD_DETECT
- See Sheet 32 of the KC705
- Digikey 296-17988-1-ND
- Bi-directional level translator
sheet 12
- See UG472 7 Series FPGAs
  Clocking Resources User Guide
- 7X5MM package
- Note these oscillators are different footprints, voltages, and outputs.
- LVDS OUT
- Mouser Part # 788-9102AI243N25E200
- LVDS
- Nominal differentail swing 1200 mV, range 250-2000mV
- differential swing 1.2 to 1.6V
- 156.25 MHz 3.3V 50ppm
- Mouser Part # 788-9120AI2D333E1562
- LVDS
- Nominal differential swing 1200 mV, range 250-2000mV
- differentail swing 1.2 to 1.6V
- 125.00 MHz 3.3V 50ppm
- Available at Arrow
sheet 13
- SFP Status Signals
- Digikey 541-1222-1-ND
- From Bank 12, KC705 Sheet 3
- Similar to Bank 117 on Sheet 9 of the KC705
- SFP+ Connector  Digikey WM1696CT-ND
- Now a dual cage is added at layout as a mechanical part.
- Digikey NDS331NCT-ND
- JUMPER
- JUMPER
- 1-3: FULL BW RX
- 2-4:  FULL BW TX
- Note Sheet 22 shows a pin 32 in error.
- 3-5: LOW BW RX
- 4-6:  LOW BW TX
- See Sheet 22 of the KC705
- 9:  SFP_TX_FAULT
- 10:  SFP_LOS
- 7-8:  SFP Enable
- 11:  SFP_MOD_DETECT
- See Sheet 32 of the KC705
- Digikey 296-17988-1-ND
- Bi-directional level translator
sheet 14
- 24mA source or sink per output
- 5V into 100 Ohms draws 50 mA
- 50 Ohms with 50mA dissipates 1/8 W
- 11 mA 0.03W
- Change Levels from
    3.3 to 5V
- 2.2V across LED
- 11 mA
- See Sheet 29 of KC705 for switches
- Change Levels from
   2.5 to 3.3
- See Sheet 29 of the KC705 Schematic
- Change load resistor from 50 to 100 to limit
  current to 10mA to stay within 12mA chip spec.
- Green LED Digikey 67-1549-1-ND
- From BANK 33
